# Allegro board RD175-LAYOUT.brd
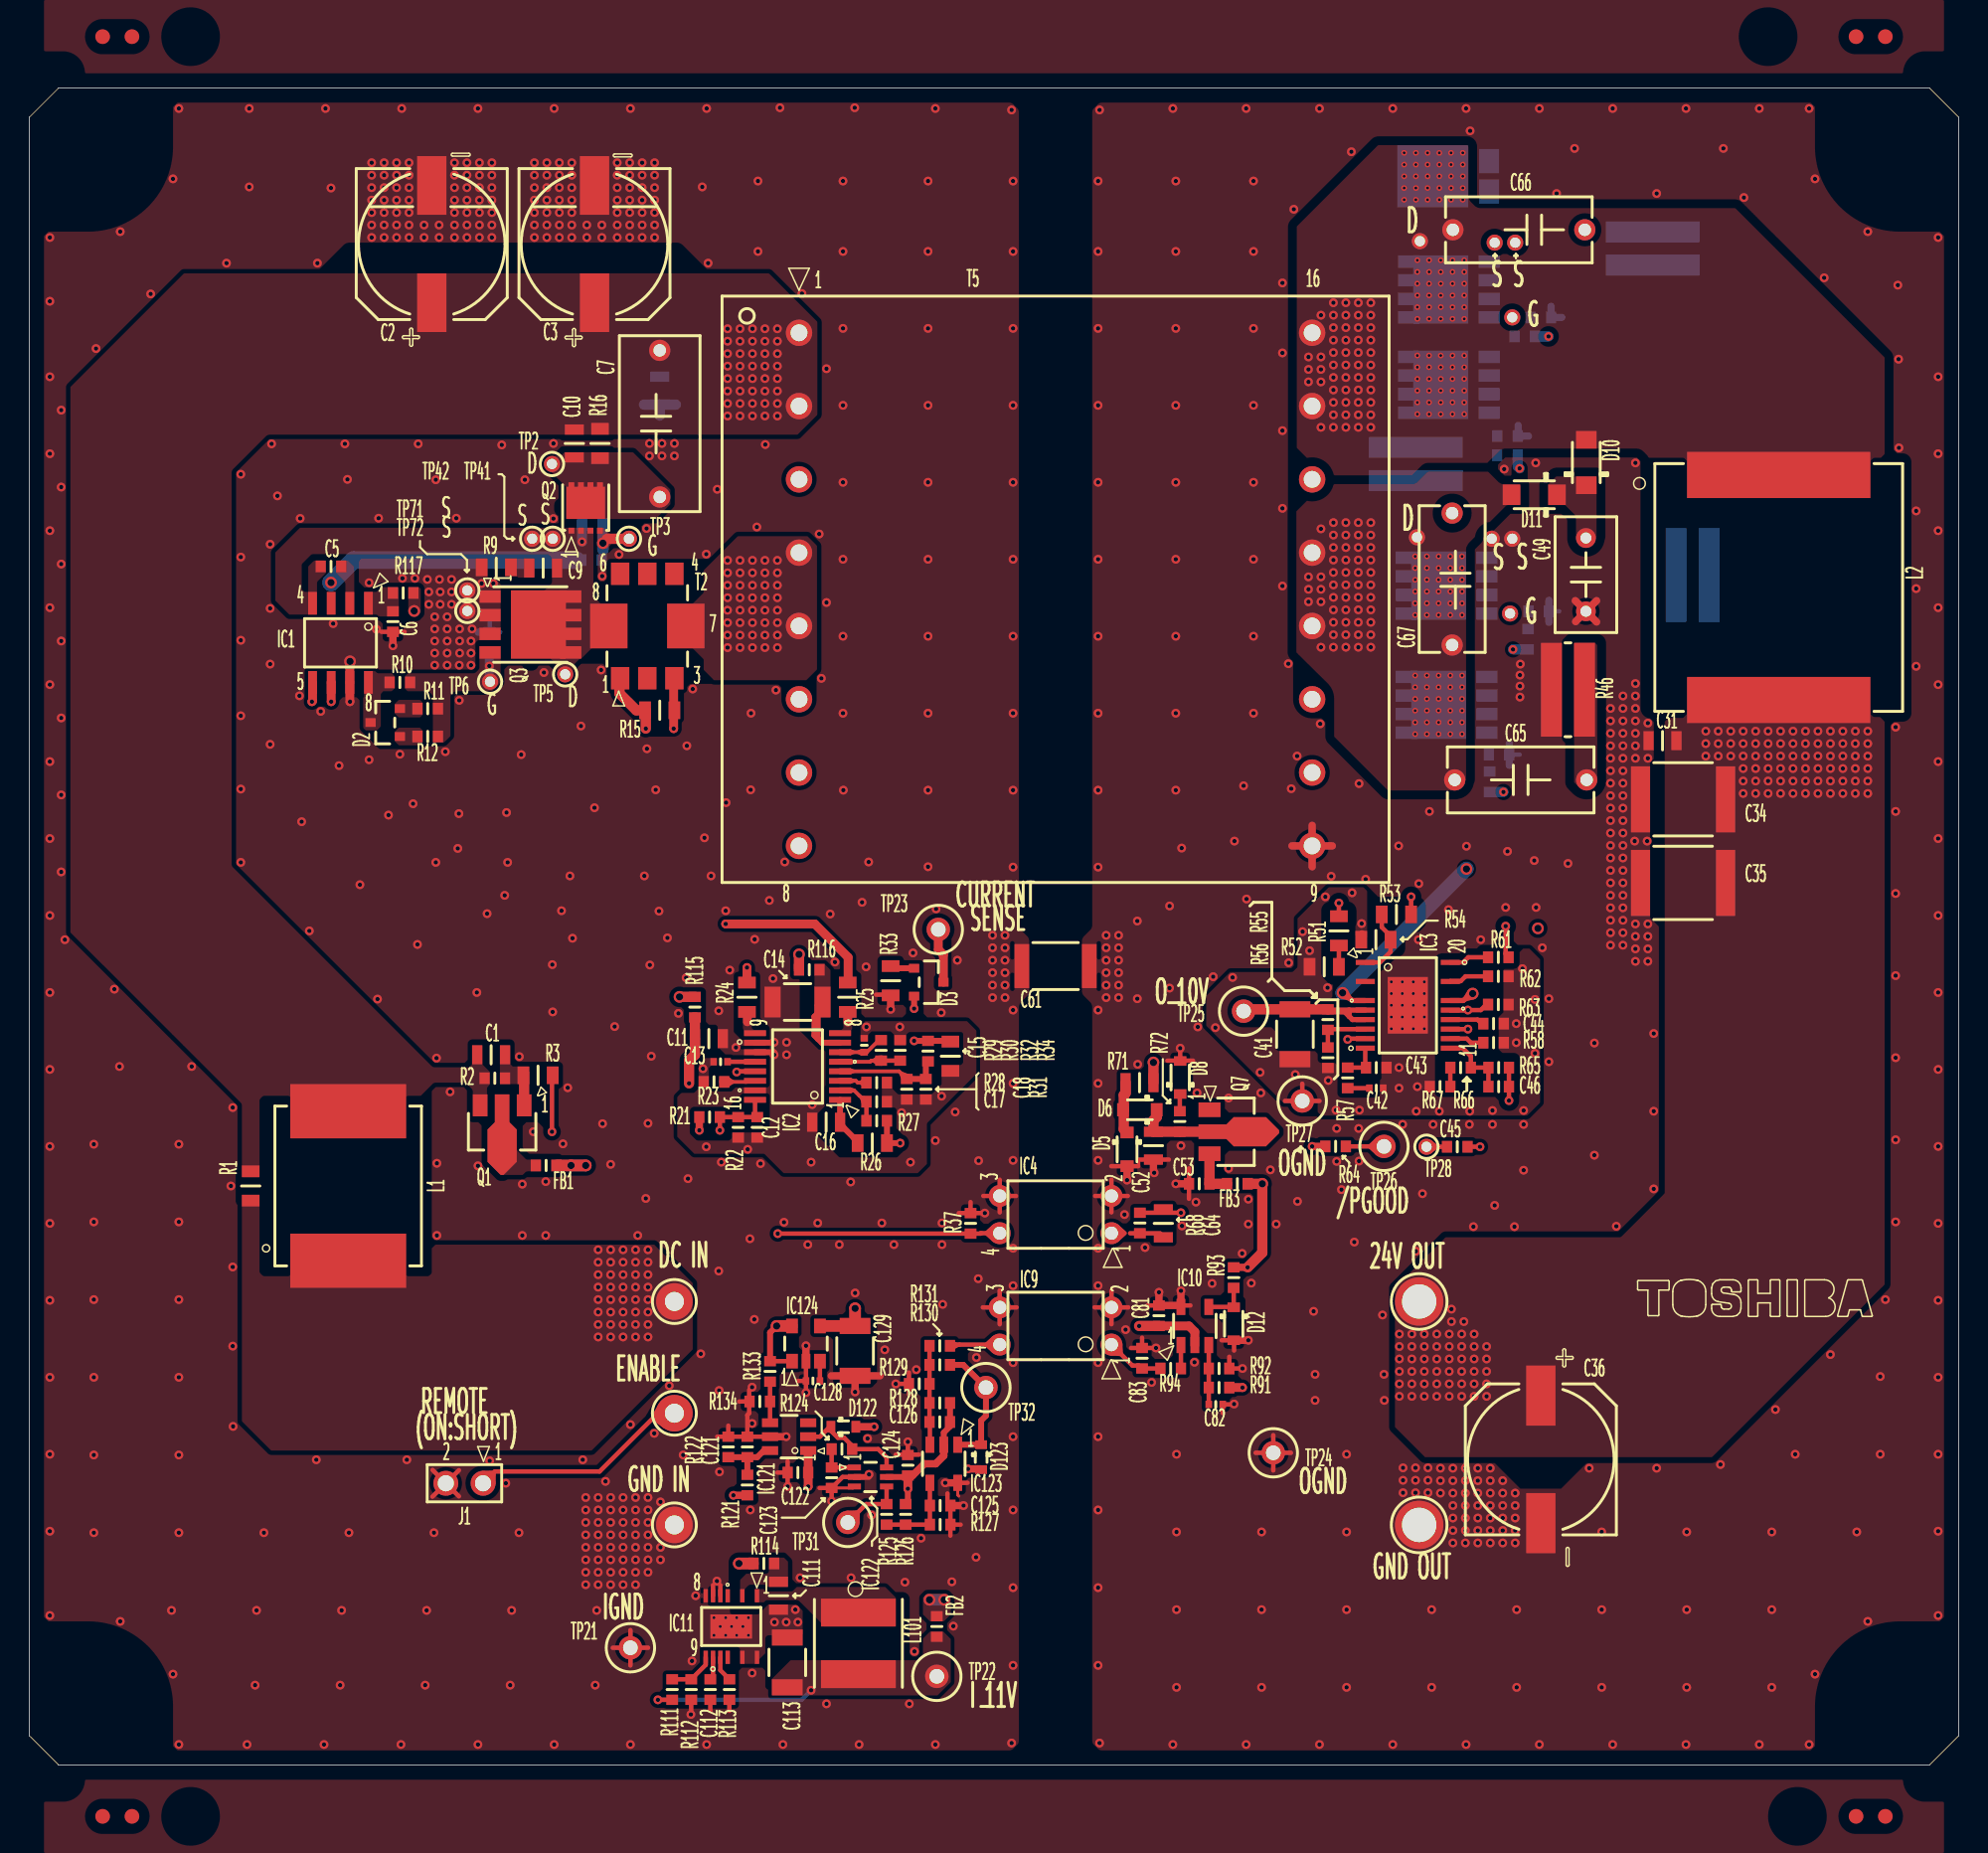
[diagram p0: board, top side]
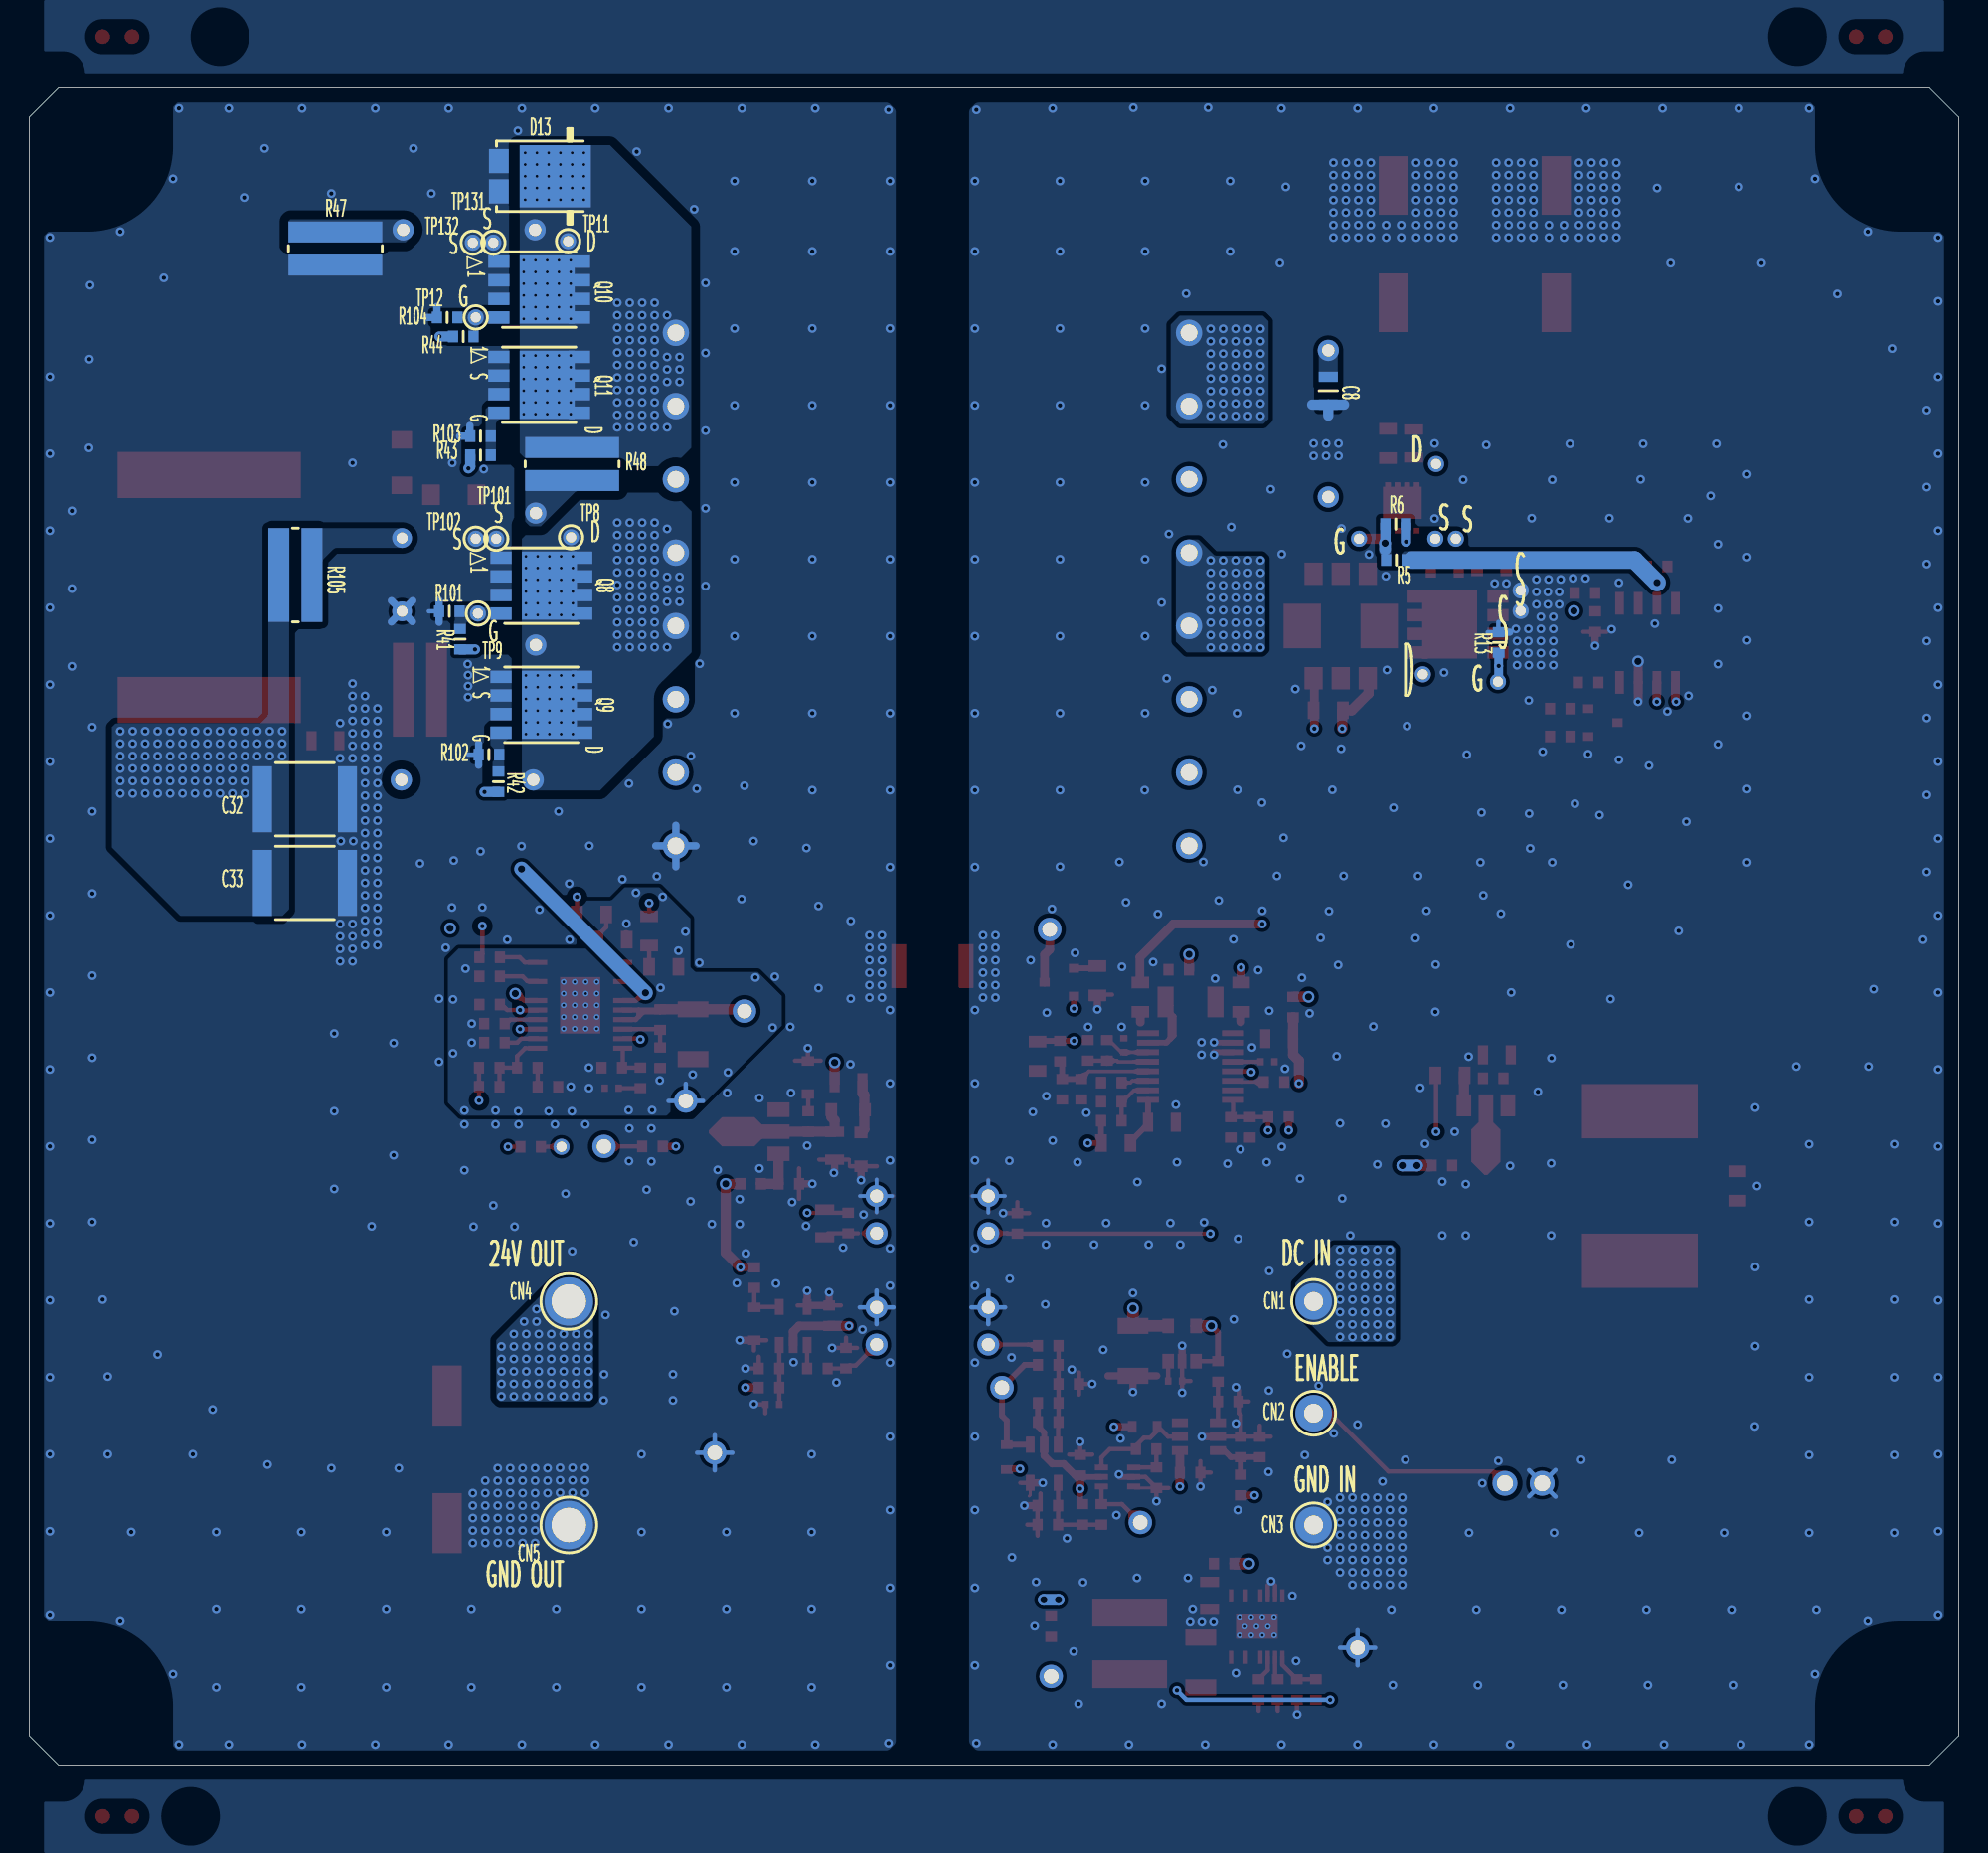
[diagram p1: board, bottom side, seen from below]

Outline 131.6 x 114.4 mm; copper layers: TOP, CONDUCTIVE2, CONDUCTIVE3, BOTTOM. Coordinates in mm from the lower left corner of the outline.
Outline path: 0,112.4 2,114.4 129.6,114.4 131.6,112.4 131.6,2 129.6,0 2,0 0,2 0,112.4

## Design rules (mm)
constraint set DEFAULT: 

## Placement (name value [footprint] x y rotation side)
C1  -  [CHIP2012_GS_1]  31.5 48.45 0 top
C2  -  [AC_S_10X12_7L_NC_2]  27.45 103.75 0 top
C3  -  [AC_S_10X12_7L_NC_2]  38.55 103.75 0 top
C5  -  [CHIP1608_GS_1]  20.57 81.76 180 top
C6  -  [CHIP1608_GS_1]  24.8 78 90 top
C7  -  [C_I_ECQE2224_F_PN]  43 91.5 270 top
C8  -  [CHIP2012_GS_1]  43 93.75 270 bottom
C9  -  [CHIP2012_GS_1]  35.05 81.65 180 top
C10  -  [CHIP2012_GS_1]  37.17 90.15 270 top
C11  -  [CHIP2012_GS_1]  46.35 49.55 0 top
C12  -  [CHIP1608_GS_1]  49.65 43.5 90 top
C13  -  [CHIP1005_GS_2]  47.15 47.98 0 top
C14  -  [CHIP3225_GS]  52.4 52.05 0 top
C15  -  [CHIP1005_GS_2]  56.95 49.1 270 top
C16  -  [CHIP2012_GS_1]  54.35 43.85 180 top
C17  -  [CHIP1608_GS_1]  57.8 45.25 180 top
C18  -  [CHIP1608_GS_1]  59.85 46.1 270 top
C31  -  [CHIP2012_GS_1]  111.4 69.88 180 top
C32  -  [CHIP5750_TD]  112.8 65.88 180 bottom
C33  -  [CHIP5750_TD]  112.8 60.17 180 bottom
C34  -  [CHIP5750_TD]  112.8 65.88 180 top
C35  -  [CHIP5750_TD]  112.8 60.17 180 top
C36  -  [AC_S_10X12_5L_PN]  103.1 20.85 180 top
C41  -  [CHIP3225_GS]  86.33 49.85 90 top
C42  -  [CHIP1005_GS_2]  91.88 46.17 0 top
C43  -  [CHIP1608_GS_1]  91.88 47.58 0 top
C44  -  [CHIP1608_GS_1]  99.88 50.58 0 top
C45  -  [CHIP1608_GS_1]  97.4 42.17 180 top
C46  -  [CHIP1608_GS_1]  100.22 46.27 180 top
C49  -  [C_I_ECQE2103_B_PN]  106.17 81.2 90 top
C52  -  [CHIP2012_GS_1]  76.67 42.25 270 top
C53  -  [CHIP1608_GS_1]  79.8 39.65 180 top
C61  -  [CHIP4632_AV]  70 54.5 0 top
C64  -  [CHIP2012_GS_1]  77.35 36.95 270 top
C65  -  [C_I_ECQE6222_F_PN]  101.72 67.2 180 top
C66  -  [C_I_ECQE6222_F_PN]  101.6 104.72 180 top
C67  -  [C_I_ECQE6222_F_PN]  97.05 80.9 270 top
C81  -  [CHIP1608_GS_1]  77.05 30.65 270 top
C82  -  [CHIP1005_GS_2]  80.92 24.6 0 top
C83  -  [CHIP1608_GS_1]  75.9 27.75 270 top
C111  -  [CHIP2012_GS_1]  51.1 11.55 270 top
C112  -  [CHIP1608_GS_1]  46.45 5.15 90 top
C113  -  [CHIP3225_GS]  51.7 7 90 top
C121  -  [CHIP1608_GS_1]  48.98 21.7 270 top
C122  -  [CHIP1608_GS_1]  52.42 19.95 180 top
C123  -  [CHIP1608_GS_1]  54.73 19.6 90 top
C124  -  [CHIP1608_GS_1]  59.92 20.45 90 top
C125  -  [CHIP1608_GS_1]  62.12 17.7 180 top
C126  -  [CHIP1608_GS_1]  62.1 23.4 0 top
C128  -  [CHIP1005_GS_2]  53.45 26.2 0 top
C129  -  [CHIP3225_GS]  56.33 28.25 90 top
CN1  -  [TP_I_6834_0_00__00_0_1]  44 31.62 90 bottom
CN2  -  [TP_I_6834_0_00__00_0_1]  44 24 270 bottom
CN3  -  [TP_I_6834_0_00__00_0_1]  44 16.38 270 bottom
CN4  -  [TP_I_8237_0_05__00_0_1]  94.8 31.62 180 bottom
CN5  -  [TP_I_8237_0_05__00_0_1]  94.8 16.38 180 bottom
D2  -  [DI_S_SOT23_3_0_95_TS]  24.27 71.11 90 top
D3  -  [DI_S_SOT23_3_0_95_TS]  61.35 53.4 270 top
D5  -  [DI_S_SOD323_2_TS_A]  74.88 42 270 top
D6  -  [DI_S_SOD323_2_TS_A]  75.75 44.7 180 top
D8  -  [ZD_S_SOD323_2_OS_A]  78.5 46.9 90 top
D10  -  [DI_S_SOD123W_TW]  106.2 88.85 90 top
D11  -  [DI_S_SOD123W_TW]  102.65 86.65 180 top
D12  -  [ZD_S_SOD323_2_OS_A]  82.15 30.1 270 top
D13  -  [DI_S_FSV10150V_OS]  96.78 108.38 0 bottom
D122  -  [DI_S_SOD523_2_RM]  55.52 23.07 180 top
D123  -  [DI_S_SOD523_2_RM]  64.92 21 90 top
FB1  -  [CHIP1608_GS_1]  35.25 40.9 0 top
FB2  -  [CHIP1608_GS_1]  61.9 9.45 270 top
FB3  -  [CHIP1608_GS_1]  82.4 39.65 180 top
IC1  -  [IC_S_SOP_8_1_27_TI]  21.23 76.55 180 top
IC2  -  [IC_S_SOP_16_0_65_GS__1]  52.4 47.65 90 top
IC3  -  [IC_S_SOP_16_20_E_0_6_1]  94.03 51.83 270 top
IC4  -  [PH_I_TLP785_TS_1]  70 37.55 90 top
IC9  -  [PH_I_TLP785_TS_1]  70 29.95 90 top
IC10  -  [IC_S_SOT23_5_0_95_TI]  79.5 29.95 0 top
IC11  -  [IC_S_SOP_16_0_5_LT_1]  47.88 9.45 180 top
IC121  -  [IC_S_SOT23_6_0_95_TI_1]  51.83 22.4 90 top
IC122  -  [IC_S_SC70_6_0_65_TI]  57.38 19.65 270 top
IC123  -  [IC_S_SOT23_5_0_95_TI]  62.38 20.55 180 top
IC124  -  [IC_S_SOP_5_0_95_TS]  52.98 28.75 0 top
J1  -  [HP_I_FFC_2AMEP1_HN]  29.68 19.22 180 top
L1  -  [L_S_ETQP5M__YLC_PN]  21.75 39.5 270 top
L2  -  [L_S_SRP1770TA_BO]  119.33 80.33 270 top
L101  -  [L_S_VLS6045EX_TD]  56.55 8.3 270 top
NOREF  -  []  109.7 30.65 0 top
NOREF#2  -  [unnamed#2]  5 117.9 0 top
NOREF#3  -  []  -5 -30 0 top
NOREF#4  -  [unnamed#2]  126.6 -3.5 180 top
NOREF#5  -  []  120.6 -3.5 0 top
NOREF#6  -  []  118.6 117.9 0 top
NOREF#7  -  []  127.6 4 0 top
NOREF#8  -  []  11 -3.5 0 top
NOREF#9  -  []  127.6 110.4 0 top
NOREF#10  -  []  4 110.4 0 top
NOREF#11  -  []  4 4 0 top
NOREF#12  -  [unnamed#2]  126.6 117.9 180 top
NOREF#13  -  []  2.35 -35.4 0 top
NOREF#14  -  [unnamed#2]  5 -3.5 0 top
NOREF#15  -  []  11 117.9 0 top
Q1  -  [TR_S_SC62_3_1_5_TS]  32.25 43.2 180 top
Q2  -  [TR_S_SON_ADVANCE_TS__1]  37.95 85.78 0 top
Q3  -  [TR_S_SOP_ADVANCE_TS__1]  34.17 77.8 270 top
Q7  -  [TR_S_SC62_3_1_5_TS]  82.3 43.2 270 top
Q8  -  [TR_S_SOP_ADVANCE_TS__1]  96.67 80.45 270 bottom
Q9  -  [TR_S_SOP_ADVANCE_TS__1]  96.67 72.33 270 bottom
Q10  -  [TR_S_SOP_ADVANCE_TS__1]  96.83 100.65 270 bottom
Q11  -  [TR_S_SOP_ADVANCE_TS__1]  96.83 94.15 270 bottom
R1  -  [CHIP2012_GS_2]  15.1 39.5 270 top
R2  -  [CHIP1608_GS_1]  31.75 46.85 0 top
R3  -  [CHIP2012_GS_2]  34.7 47.05 180 top
R5  -  [CHIP1608_GS_1]  38.35 82.2 0 bottom
R6  -  [CHIP1608_GS_1]  38.4 84.65 180 bottom
R9  -  [CHIP2012_GS_2]  31.85 81.7 180 top
R10  -  [CHIP1608_GS_1]  25.27 73.85 180 top
R11  -  [CHIP1608_GS_1]  27.18 72.06 0 top
R12  -  [CHIP1608_GS_1]  27.18 70.16 0 top
R13  -  [CHIP1608_GS_1]  31.38 76.58 90 bottom
R15  -  [CHIP2012_GS_2]  43 71.95 0 top
R16  -  [CHIP2012_GS_2]  38.92 90.15 270 top
R21  -  [CHIP1608_GS_1]  46.4 44.2 0 top
R22  -  [CHIP1608_GS_1]  48.35 43.5 270 top
R23  -  [CHIP1608_GS_1]  46.7 46.6 0 top
R24  -  [CHIP2012_GS_2]  48.95 52.38 270 top
R25  -  [CHIP2012_GS_2]  55.83 52.38 270 top
R26  -  [CHIP2012_GS_2]  57.5 42.42 180 top
R27  -  [CHIP1608_GS_1]  57.8 43.95 180 top
R28  -  [CHIP1608_GS_1]  57.8 46.55 180 top
R29  -  [CHIP1608_GS_1]  58.1 48.75 90 top
R30  -  [CHIP1608_GS_1]  59.4 48.75 270 top
R31  -  [CHIP1608_GS_1]  61.15 46.1 90 top
R32  -  [CHIP1608_GS_1]  61.3 48.7 270 top
R33  -  [CHIP2012_GS_2]  58.75 53.5 90 top
R34  -  [CHIP2012_GS_2]  62.83 48.35 270 top
R37  -  [CHIP1608_GS_1]  64.2 36.95 90 top
R41  -  [CHIP1608_GS_1]  102.22 76.8 270 bottom
R42  -  [CHIP1608_GS_1]  99.6 67.08 270 bottom
R43  -  [CHIP1608_GS_1]  100.83 89.35 0 bottom
R44  -  [CHIP1608_GS_1]  102 97.45 0 bottom
R46  -  [R_S_LTR100_RM]  104.95 73.35 180 top
R47  -  [R_S_LTR100_RM]  110.72 103.45 270 bottom
R48  -  [R_S_LTR100_RM]  94.58 88.75 270 bottom
R51  -  [CHIP2012_GS_2]  89.33 56.9 90 top
R52  -  [CHIP2012_GS_2]  88.33 54.45 0 top
R53  -  [CHIP2012_GS_2]  93.25 58.02 0 top
R54  -  [CHIP2012_GS_2]  91.85 56.3 0 top
R55  -  [CHIP1608_GS_1]  88.58 50.85 90 top
R56  -  [CHIP1608_GS_1]  88.58 48.25 90 top
R57  -  [CHIP1608_GS_1]  89.92 46.88 90 top
R58  -  [CHIP1608_GS_1]  99.88 49.27 180 top
R61  -  [CHIP1608_GS_1]  100.2 55.1 0 top
R62  -  [CHIP1608_GS_1]  100.2 53.8 0 top
R63  -  [CHIP1608_GS_1]  100.2 51.88 180 top
R64  -  [CHIP1608_GS_1]  89.1 42.2 180 top
R65  -  [CHIP1608_GS_1]  100.22 47.58 0 top
R66  -  [CHIP1608_GS_1]  97.62 47.58 0 top
R67  -  [CHIP1608_GS_1]  96.22 46.27 0 top
R68  -  [CHIP1608_GS_1]  75.75 36.98 270 top
R71  -  [CHIP2012_GS_1]  75.72 46.55 180 top
R72  -  [CHIP1608_GS_1]  78.47 43.9 270 top
R91  -  [CHIP1608_GS_1]  81.15 25.75 180 top
R92  -  [CHIP1608_GS_1]  81.15 27.05 180 top
R93  -  [CHIP1608_GS_1]  82.15 33.25 90 top
R94  -  [CHIP1608_GS_1]  77.85 27.05 0 top
R101  -  [CHIP1608_GS_1]  102.95 78.7 180 bottom
R102  -  [CHIP1608_GS_1]  100.25 68.92 180 bottom
R103  -  [CHIP1608_GS_1]  100.83 90.65 180 bottom
R104  -  [CHIP1608_GS_1]  103.1 98.75 180 bottom
R105  -  [R_S_LTR100_RM]  113.45 81.17 180 bottom
R111  -  [CHIP1608_GS_1]  43.85 5.15 270 top
R112  -  [CHIP1608_GS_1]  45.15 5.15 270 top
R113  -  [CHIP1608_GS_1]  47.75 5.15 270 top
R114  -  [CHIP1608_GS_1]  50.1 13.75 180 top
R115  -  [CHIP1608_GS_1]  45.4 51.7 90 top
R116  -  [CHIP1608_GS_1]  53.2 54.25 180 top
R117  -  [CHIP1608_GS_1]  25.5 79.95 0 top
R121  -  [CHIP1608_GS_1]  48.98 19.1 90 top
R122  -  [CHIP1608_GS_1]  47.67 21.7 90 top
R124  -  [CHIP1608_GS_1]  55.42 21.55 0 top
R125  -  [CHIP1608_GS_1]  58.48 17.1 90 top
R126  -  [CHIP1608_GS_1]  59.77 17.1 90 top
R127  -  [CHIP1608_GS_1]  62.12 16.4 180 top
R128  -  [CHIP1608_GS_1]  62.1 24.7 0 top
R129  -  [CHIP1608_GS_1]  60.7 26 0 top
R130  -  [CHIP1608_GS_1]  62.1 27.3 180 top
R131  -  [CHIP1608_GS_1]  62.1 28.6 180 top
R133  -  [CHIP1608_GS_1]  50.52 26.85 270 top
R134  -  [CHIP1608_GS_1]  49.83 24.8 180 top
T2  -  [T_S_53__C_MU]  42.15 77.7 0 top
T5  -  [T_I_BEER35_1116CPHFR_1]  70 80.2 0 top
TP2  -  [TP_I_TH0_7_LC1_1_RC1_1]  35.65 88.75 0 top
TP3  -  [TP_I_TH0_7_LC1_1_RC1_1]  40.9 83.65 0 top
TP5  -  [TP_I_TH0_7_LC1_1_RC1_1]  36.55 74.4 0 top
TP6  -  [TP_I_TH0_7_LC1_1_RC1_1]  31.43 73.9 0 top
TP8  -  [TP_I_TH0_7_LC1_1_RC1_1]  94.65 83.75 90 bottom
TP9  -  [TP_I_TH0_7_LC1_1_RC1_1]  101 78.55 270 bottom
TP11  -  [TP_I_TH0_7_LC1_1_RC1_1]  94.85 103.95 180 bottom
TP12  -  [TP_I_TH0_7_LC1_1_RC1_1]  101.15 98.75 180 bottom
TP21  -  [TP_I_LC_22_GS]  41 8 0 top
TP22  -  [TP_I_LC_22_GS]  61.9 6.05 0 top
TP23  -  [TP_I_LC_22_GS]  62 57 0 top
TP24  -  [TP_I_LC_22_GS]  84.85 21.3 0 top
TP25  -  [TP_I_LC_22_GS]  82.83 51.42 0 top
TP26  -  [TP_I_LC_22_GS]  92.4 42.2 0 top
TP27  -  [TP_I_LC_22_GS]  86.83 45.3 0 top
TP28  -  [TP_I_TH0_7_LC1_1_RC1_1]  95.3 42.17 0 top
TP31  -  [TP_I_LC_22_GS]  55.83 16.55 0 top
TP32  -  [TP_I_LC_22_GS]  65.25 25.75 0 top
TP41  -  [TP_I_TH0_7_LC1_1_RC1_1]  35.7 83.65 0 top
TP42  -  [TP_I_TH0_7_LC1_1_RC1_1]  34.3 83.65 0 top
TP71  -  [TP_I_TH0_7_LC1_1_RC1_1]  29.88 80.12 0 top
TP72  -  [TP_I_TH0_7_LC1_1_RC1_1]  29.88 78.72 0 top
TP101  -  [TP_I_TH0_7_LC1_1_RC1_1]  99.75 83.65 180 bottom
TP102  -  [TP_I_TH0_7_LC1_1_RC1_1]  101.15 83.65 180 bottom
TP131  -  [TP_I_TH0_7_LC1_1_RC1_1]  99.95 103.85 180 bottom
TP132  -  [TP_I_TH0_7_LC1_1_RC1_1]  101.35 103.85 180 bottom

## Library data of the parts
C1 C8-C11 C16 C31 C52 C64 C111 R71 = Chip2012_GS_1
C2 C3 = PCV2A180MCL1_NC
C5 C6 C12 C17 C18 C43-C46 C53 C81 C83 C112 C121-C126 FB1-FB3 R2 R5 R6 R10-R13 R21-R23 R27-R32 R37 R41-R44 R55-R58 R61-R68 R72 R91-R94 R101-R104 R111-R117 R121 R122 R124-R131 R133 R134 = Chip1608_GS_1
C7 = ECQE2224*F_PN
C13 C15 C42 C82 C128 = Chip1005_GS_2
C14 C41 C113 C129 = Chip3225_GS
C32-C35 = Chip5750_TD: alternate symbols: (C34_Chip5750_TD)
C36 = EEHZS1V331P_PN
C49 = ECQE2103*B_PN
C61 = Chip4632_AV
C65-C67 = ECQE6222*F_PN
CN1-CN3 = 6834-0-00-**-00-00-03-0_ML
CN4 CN5 = 8237-0-05-**-00-00-03-0_ML
D2 D3 = TBAT54S_TS
D5 D6 = BAS316_TS_A
D8 D12 = MM3Z***ST1G_OS_A
D10 D11 = SS220LW_TW
D13 = FSV10150V_OS: alternate symbols: (T:DI_S_FSV10150V_OS;B:DI_S_FSV10150V_OS,D13_DI_S_FSV10150V_O_1)
D122 D123 = RB520SM-30_RM
IC1 = UCC272**AD_TI
IC2 = LM5025CMTC_GS
IC3 = LT8311*FE_GS
IC4 IC9 = TLP785_TS_1
IC10 IC123 = TLV7211AIDBVR_TI
IC11 = LTC3630AIM_LT_1
IC121 = TPS3779*DBV_TI_1
IC122 = SN74LVC1G97DCK_TI
IC124 = TAR5S**_TS
J1 = FFC-2AMEP1_HN
L1 = ETQP5M***YLC_PN: alternate symbols: (L1_L_S_ETQP5M__YLC_P_1)
L2 = SRP1770TA_BO
L101 = VLS6045EX_TD
Q1 = 2SA1201_TS
Q2 = TPN5900CNH_TS
Q3 = TPH3300CNH_TS_A
Q7 = 2SC5810_TS
Q8-Q11 = TPH9R00CQH_TS_A
R1 R3 R9 R15 R16 R24-R26 R33 R34 R51-R54 = Chip2012_GS_2
R46-R48 R105 = LTR100_RM: alternate symbols: (T:R_S_LTR100_RM,R46_R_S_LTR100_RM;B:R_S_LTR100_RM,R105_R_S_LTR100_RM,R47_R_S_LTR100_RM,R48_R_S_LTR100_RM)
T2 = 53***C_MU
T5 = BEER35-1116CPHFR_GS
TP2 TP3 TP5 TP6 TP8 TP9 TP11 TP12 TP28 TP41 TP42 TP71 TP72 TP101 TP102 TP131 TP132 = TP_I_TH0.7_LC1.1_RC1.2_GS
TP21-TP27 TP31 TP32 = LC-22_GS

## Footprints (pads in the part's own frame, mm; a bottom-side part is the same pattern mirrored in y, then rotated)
AC_S_10X12_5L_PN
  rect 2x4.1 smd: 1(0,-4.35) 2(0,4.35)
AC_S_10X12_7L_NC_2
  rect 2x4 smd: 1(0,-4) 2(0,4)
C_I_ECQE2103_B_PN
  round 1.35 hole 0.75: 1(-2.5,0) 2(2.5,0)
C_I_ECQE2224_F_PN
  round 1.45 hole 0.85: 1(-5,0) 2(5,0)
C_I_ECQE6222_F_PN
  round 1.45 hole 0.85: 1(-4.5,0) 2(4.5,0)
CHIP1005_GS_2
  rect 0.45x0.5 smd: 1(-0.475,0) 2(0.475,0)
CHIP1608_GS_1
  rect 0.7x0.8 smd: 1(-0.7,0) 2(0.7,0)
CHIP2012_GS_1
  rect 0.7x1.3 smd: 1(-0.95,0) 2(0.95,0)
CHIP2012_GS_2
  rect 0.8x1.2 smd: 1(-1,0) 2(1,0)
CHIP3225_GS
  rect 1.1x2.1 smd: 1(-1.7,0) 2(1.7,0)
CHIP4632_AV
  rect 1x3 smd: 1(-2.3,0) 2(2.3,0)
CHIP5750_TD
  rect 1.3x4.5 smd: 1(-2.9,0) 2(2.9,0)
DI_S_FSV10150V_OS
  rect 1.35x1.65 smd: 1(2.8,1.035) 2(2.8,-1.035)
  custom 1.062x1.062 smd: 3(-1.05,0)
DI_S_SOD123W_TW
  rect 1.2x1.4 smd: 1(1.55,0) 2(-1.55,0)
DI_S_SOD323_2_TS_A
  rect 0.8x0.9 smd: 1(1.15,0) 2(-1.15,0)
DI_S_SOD523_2_RM
  rect 0.6x0.8 smd: 1(-0.85,0) 2(0.85,0)
DI_S_SOT23_3_0_95_TS
  rect 0.6x0.7 smd: 1(-0.95,-1) 2(0.95,-1) 3(0,1)
HP_I_FFC_2AMEP1_HN
  round 1.7 hole 1.1: 1(-1.27,0) 2(1.27,0)
IC_S_SC70_6_0_65_TI
  rect 0.4x0.9 smd: 1(-0.65,-1.1) 2(0,-1.1) 3(0.65,-1.1) 4(0.65,1.1) 5(0,1.1) 6(-0.65,1.1)
IC_S_SOP_5_0_95_TS
  rect 0.8x1 smd: 1(-0.95,-1.2) 3(0.95,-1.2) 4(0.95,1.2) 5(-0.95,1.2)
  rect 0.6x1 smd: 2(0,-1.2)
IC_S_SOP_8_1_27_TI
  rect 0.6x1.55 smd: 1(-1.905,-2.7) 2(-0.635,-2.7) 3(0.635,-2.7) 4(1.905,-2.7) 5(1.905,2.7) 6(0.635,2.7) 7(-0.635,2.7) 8(-1.905,2.7)
IC_S_SOP_16_0_5_LT_1
  rect 0.3x0.9 smd: 1(-1.76,-2.1) 3(-0.76,-2.1) 5(0.239,-2.1) 6(0.74,-2.1) 7(1.24,-2.1) 8(1.74,-2.1) 9(1.74,2.1) 10(1.24,2.1) 11(0.74,2.1) 12(0.239,2.1) 14(-0.76,2.1) 16(-1.76,2.1)
  custom 0.413x0.413 smd: EP(0,0)
IC_S_SOP_16_0_65_GS__1
  rect 0.4x1.5 smd: 1(-2.275,-2.9) 2(-1.625,-2.9) 3(-0.975,-2.9) 4(-0.325,-2.9) 5(0.325,-2.9) 6(0.975,-2.9) 7(1.625,-2.9) 8(2.275,-2.9) 9(2.275,2.9) 10(1.625,2.9) 11(0.975,2.9) 12(0.325,2.9) 13(-0.325,2.9) 14(-0.975,2.9) 15(-1.625,2.9) 16(-2.275,2.9)
IC_S_SOP_16_20_E_0_6_1
  rect 0.35x1.3 smd: 1(-2.925,-2.9) 3(-1.625,-2.9) 5(-0.325,-2.9) 6(0.325,-2.9) 7(0.975,-2.9) 8(1.625,-2.9) 9(2.275,-2.9) 10(2.925,-2.9) 11(2.925,2.9) 12(2.275,2.9) 13(1.625,2.9) 14(0.975,2.9) 15(0.325,2.9) 16(-0.325,2.9) 18(-1.625,2.9) 20(-2.925,2.9)
  custom 0.685x0.685 smd: E(0,0)
IC_S_SOT23_5_0_95_TI
  rect 0.6x1.1 smd: 1(-0.95,-1.3) 2(0,-1.3) 3(0.95,-1.3) 4(0.95,1.3) 5(-0.95,1.3)
IC_S_SOT23_6_0_95_TI_1
  rect 0.6x1.1 smd: 1(-0.95,-1.3) 2(0,-1.3) 3(0.95,-1.3) 4(0.95,1.3) 5(0,1.3) 6(-0.95,1.3)
L_S_ETQP5M__YLC_PN
  custom 0.925x0.925 smd: 1(5.1,0) 2(-5.1,0)
L_S_SRP1770TA_BO
  custom 0.787x0.787 smd: 1(-7.675,0) 2(7.675,0)
L_S_VLS6045EX_TD
  rect 1.9x5.1 smd: 1(-2.1,0) 2(2.1,0)
PH_I_TLP785_TS_1
  round 1.5 hole 0.9: 1(-1.27,-3.81) 2(1.27,-3.81) 3(1.27,3.81) 4(-1.27,3.81)
R_S_LTR100_RM
  custom 0.357x0.357 smd: 1(-1.13,0) 2(1.13,0)
T_I_BEER35_1116CPHFR_1
  round 1.8 hole 1.15: 1(-17.5,17.5) 2(-17.5,12.5) 3(-17.5,7.5) 4(-17.5,2.5) 5(-17.5,-2.5) 6(-17.5,-7.5) 7(-17.5,-12.5) 8(-17.5,-17.5) 9(17.5,-17.5) 10(17.5,-12.5) 11(17.5,-7.5) 12(17.5,-2.5) 13(17.5,2.5) 14(17.5,7.5) 15(17.5,12.5) 16(17.5,17.5)
T_S_53__C_MU
  custom 0.312x0.312 smd: 1(-1.85,-3.562) 2(0,-3.562) 3(1.85,-3.562) 4(1.85,3.562) 5(0,3.562) 6(-1.85,3.562)
  custom 0.637x0.637 smd: 7(2.625,0) 8(-2.625,0)
TP_I_6834_0_00__00_0_1
  round 2.5 hole 1.3: 1(0,0)
TP_I_8237_0_05__00_0_1
  round 3.3 hole 2.34: 1(0,0)
TP_I_LC_22_GS
  round 1.6 hole 1: 1(0,0)
TP_I_TH0_7_LC1_1_RC1_1
  round 1.1 hole 0.7: 1(0,0)
TR_S_SC62_3_1_5_TS
  rect 1x1.5 smd: 1(-1.5,-1.8) 3(1.5,-1.8)
  custom 0.5x0.5 smd: 2(0,0.2)
TR_S_SON_ADVANCE_TS__1
  rect 0.4x0.4 smd: (-0.975,1.525) (-0.975,-1.575) (-0.325,1.525) (0.325,1.525) (0.325,-1.575) (0.975,1.525) G(0.975,-1.575) S(-0.325,-1.575)
  custom 0.55x0.55 smd: D(0,0.325)
TR_S_SOP_ADVANCE_TS__1
  rect 0.85x1.45 smd: (-1.905,2.75) (-1.905,-2.75) (-0.635,2.75) (0.635,2.75) (0.635,-2.75) (1.905,2.75) G(1.905,-2.75) S(-0.635,-2.75)
  custom 0.938x0.938 smd: D(0,0.55)
unnamed#2
  round 1 smd: (0,0) (2,0)
ZD_S_SOD323_2_OS_A
  rect 0.65x0.85 smd: 1(1.125,0) 2(-1.125,0)

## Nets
VIN: FB1.2 R114.2 R115.2 R121.1
I_11V: FB2.1 IC124.1 IC124.5 R116.2 R117.2 R133.1
IGND: C2.2 C3.2 C6.1 C8.2 C11.2 C12.1 C13.1 C14.1 C15.1 C16.2 C17.1 C18.2 C61.1 C111.2 C112.1 C113.2 C121.1 C122.2 C123.1 C124.2 C125.1 C128.1 C129.1 CN3.1 IC1.7 IC2.10 IC2.11 IC2.15 IC4.3 IC9.3 IC11.6 IC11.7 IC11.8 IC11.14 IC11.16 IC11.EP IC121.5 IC122.2 IC122.3 IC123.5 IC124.2 J1.2 Q3.S R9.2 R13.2 R15.1 R22.2 R23.1 R28.1 R30.1 R31.1 R33.1 R34.2 R37.2 R112.2 R113.2 R122.2 R127.1 R129.1 R134.2 T2.1 TP21.1 TP71.1 TP72.1
O_10V: C41.2 C81.2 FB3.1 IC3.6 IC3.7 IC10.2 R55.2 R64.2 R93.2 TP25.1
OGND: C31.2 C32.2 C33.2 C34.2 C35.2 C36.2 C41.1 C42.2 C43.2 C44.2 C49.1 C52.2 C53.2 C61.2 C81.1 C82.2 C83.1 CN5.1 D5.1 D8.1 D12.1 D13.1 D13.2 IC3.E IC4.2 IC9.2 IC10.5 Q8.S Q9.S Q10.S Q11.S R46.2 R47.2 R52.1 R54.1 R56.1 R58.1 R62.2 R63.1 R67.1 R92.1 R101.1 R102.1 R103.1 R104.1 T5.9 TP24.1 TP27.1 TP101.1 TP102.1 TP131.1 TP132.1
N551925: Q10.G R44.1 R104.2 TP12.1
N551939: C66.2 D10.1 D13.3 L2.1 Q10.D Q11.D R48.1 R53.2 R61.2 T5.15 T5.16 TP11.1
N551985: T2.7 T5.4 T5.5
N552199: C31.1 C32.1 C33.1 C34.1 C35.1 C36.1 C46.1 CN4.1 L2.2 R65.2 R91.1 R105.1
N552352: C1.1 C2.1 C3.1 C7.1 C8.1 C10.1 L1.2 Q1.3 R1.1 R2.1 R16.1 T5.1 T5.2
N552464: C65.2 C67.2 D11.1 Q8.D Q9.D R51.2 T5.12 T5.13 TP8.1
N552846: R71.1 T5.10
N556504: Q9.G R42.1 R102.2
N560012: Q8.G R41.1 R101.2 TP9.1
N560018: Q2.G R5.2 R6.1 TP3.1
N560020: IC1.6 R25.1
N560028: C1.2 Q1.1 R2.2 R3.2
N560032: C52.1 D6.2 Q7.2 R72.2
N560040: IC3.8 R55.1 R56.2
N560044: IC3.16 R43.2 R44.2
N560052: IC2.9 R24.2
N560054: FB1.1 Q1.2
N560056: Q3.G R10.1 R11.2 R12.2 R13.1 TP6.1
N560060: C121.2 IC121.6 R121.2 R122.1
N560066: C64.1 IC3.9 R68.1
N560076: C5.2 C9.1 IC1.4 Q2.S Q3.D R6.2 T2.8 TP5.1 TP41.1 TP42.1
N560080: IC3.5 R41.2 R42.2
N560082: IC3.18 R62.1
N560106: C53.1 FB3.2 Q7.3
N560114: C44.1 IC3.14
N560120: D3.3 R15.2 T2.3 TP23.1
N560124: C45.1 IC3.15 R63.2
N560134: C11.1 R21.1 R26.1 R27.1 R115.1
N560136: C64.2 IC4.1 R68.2
N560152: IC3.13 R64.1 TP26.1
N560170: IC3.3 R51.1 R52.2
N560174: D2.3 IC1.8 R10.2
N560178: C46.2 IC3.11 R65.1 R66.2
N560180: C122.1 C124.1 C126.2 C129.2 IC121.1 IC122.5 IC123.2 IC124.4 R126.2 R128.2
N560194: C43.1 IC3.10 R57.2
N560196: C7.2 C10.2 Q2.D R16.2 TP2.1
N560198: C13.2 IC2.12
N560204: C12.2 D122.1 D123.1 IC2.16 R21.2 R22.1
N560212: R66.1 R67.2
N560214: C113.1 FB2.2 L101.2 R111.2 TP22.1
N560216: D2.2 R11.1
N560218: D3.1 R33.2
N560224: Q11.G R43.1 R103.2
N560238: C18.1 IC2.4 R31.2 R32.2
N560240: IC3.12 R58.2
N560246: IC2.3 R28.2
N560250: D8.2 Q7.1 R72.1
N560270: C15.2 IC2.6 R29.2
N560286: C6.2 IC1.1 R117.1
N560290: C14.2 IC2.7 R116.1
N560306: IC2.13 IC4.4 R37.1
N560310: CN1.1 L1.1 R1.2
N560318: C5.1 IC1.2
N560366: IC1.3 R5.1
N560368: IC2.5 R29.1 R30.2
N560372: IC3.1 R53.1 R54.2
N560402: CN2.1 J1.1 R3.1
N560442: C17.2 IC2.2 R27.2
N560448: D5.2 D6.1 R71.2
N560522: D3.2 R32.1 R34.1
N560530: IC2.14 R23.2
N560656: D2.1 R12.1
N560660: IC2.8 R25.2
N560674: C42.1 R57.1
N560710: C16.1 IC2.1 R26.2
N560758: IC1.5 R24.1
N560892: IC3.20 R61.1
N568590: D122.2 IC121.2 IC122.6 R124.2
N568875: C123.2 IC122.1 R124.1
N570936: IC122.4 R125.2 TP31.1
N571063: C125.2 IC123.4 R125.1 R126.1 R127.2
N572220: C126.1 IC123.3 R128.1 R129.2 R130.2 R131.2
N572478: D123.2 IC123.1 R130.1 TP32.1
N585143: C82.1 IC10.3 R91.2 R92.2
N585161: D12.2 IC10.4 R93.1
N585197: C83.2 IC9.1 R94.1
N585311: IC10.1 R94.2
N641223: IC9.4 R131.1
N642654: C49.2 D10.2 D11.2 R105.2
N647990: C45.2 TP28.1
N3796628: C67.1 R48.2
N3799991: C65.1 R46.1
N3800429: C66.1 R47.1
N3802771: IC121.4 R133.2 R134.1
N3804597: IC11.1 L101.1
N3804695: C111.1 IC11.3 R114.1
N3805483: IC11.9 R111.1 R112.1
N3805587: C112.2 IC11.10
N3805628: IC11.11 R113.1
N3830864: C128.2 IC124.3
N3881286: C9.2 R9.1

Pads without a net: IC11 5 12; IC121 3; T2 2 4 5 6; T5 3 6 7 8 11 14

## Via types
v1: diameter 0.6, hole 0.3, TOP to BOTTOM, 1352 vias
v2: diameter 0.8, hole 0.5, TOP to BOTTOM, 19 vias
v3: diameter 0.4, hole 0.2, TOP to BOTTOM, 181 vias

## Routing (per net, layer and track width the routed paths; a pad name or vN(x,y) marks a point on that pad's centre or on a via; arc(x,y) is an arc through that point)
VIN: length 56.2
  TOP w0.5: R121.1 v1(48.02,18.4)
  TOP w0.7: R115.2 v2(44.35,52.4)
  TOP w0.8: v2(37.95,40.9) v2(36.95,40.9) 36.02,40.9 ; 49.35,13.75 v2(48.4,13.75)
  CONDUCTIVE2 w0.8: v2(36.95,40.9) v2(37.95,40.9)
  CONDUCTIVE3 w1: v2(37.95,40.9) 40.25,43.2 40.25,49.1 43.55,52.4 v2(44.35,52.4) ; v2(37.95,40.9) 39,39.85 42.55,39.85 48.2,34.2 48.2,18.57 v1(48.02,18.4) 48.02,14.12 v2(48.4,13.75) ; v2(37.95,40.9) v2(36.95,40.9)
  BOTTOM w0.8: v2(36.95,40.9) v2(37.95,40.9)
I_11V: length 129.4
  TOP w0.3: IC124.1 R133.1
  TOP w0.4: R133.1 50.52,29.5 v2(50.98,29.95)
  TOP w0.7: R116.2 v2(52.5,55.3)
  TOP w0.8: v2(50.98,29.95) 52,29.95
  CONDUCTIVE2 w0.8: v2(61.4,11.28) v2(62.4,11.28)
  CONDUCTIVE3 w1.2: v2(50.98,29.95) 50.45,29.43 50.45,16.7 55.88,11.28 v2(61.4,11.28) v2(62.4,11.28) 63.4,11.28 65.78,13.65 65.78,22 62.75,25.02 62.75,30.07 63.55,30.88 63.55,42.5 58.48,47.58 58.15,47.58 52.5,53.23 v2(52.5,55.3) 48.33,59.48 36.38,59.48 26.25,69.6 26.25,78.6
  BOTTOM w0.8: v2(62.4,11.28) v2(61.4,11.28)
  vias: v2(26.25,78.72)
IGND: length 176.7
  TOP w0.2: 63.4,18.35 63.33,18.43 IC123.5 ; IC122.3 56.17,18.9 C123.1
  TOP w0.3: C123.1 55.48,19.65 IC122.2 ; C123.1 v1(54.73,18) ; C123.1 53.9,18.9 ; 48.42,24.8 49.1,24.8 ; 49.1,24.8 49.1,25.57 ; 49.1,24.8 49.1,24 48.98,23.88 C121.1 ; IC4.3 66.19,39.92 ; IC4.3 66.19,37.7 ; IC4.3 65.08,38.82 ; IC4.3 67.3,38.82 ; R122.2 47.67,23.15 ; R122.2 46.92,22.4 ; R122.2 C121.1 ; TP21.1 41,9.2 ; TP21.1 39.8,8 ; TP21.1 42.2,8 ; TP21.1 41,6.8 ; C122.2 51.73,20.73 ; C122.2 v1(51.73,19) ; C122.2 51.02,19.95 ; 25.6,77.3 C6.1 24.02,77.3 ; R127.1 63.52,16.4 ; R127.1 62.83,15.65 ; R127.1 C125.1 62.62,17.9 62.62,18.52 ; 59.92,21.18 v1(59.92,22.05) ; 59.92,21.18 60.67,21.18 ; 59.92,21.18 59.1,21.18 ; C121.1 50.5,22.4 ; J1.2 27.5,20.12 ; J1.2 27.5,18.31 ; J1.2 29.3,18.33 ; J1.2 29.3,20.11 ; 45.15,4.46 45.15,3.7 ; R37.2 v1(65.17,37.65) ; R37.2 63.4,37.65 ; R37.2 64.2,38.4 ; IC9.3 67.34,31.22 ; IC9.3 66.19,32.37 ; IC9.3 66.19,30.07 ; IC9.3 65.04,31.22 ; 57.75,52.55 58.75,52.55 ; C112.1 46.45,3.7 ; R113.2 47.75,3.7 ; IC11.7 46.64,12.28 ; C128.1 IC124.2 ; C128.1 52.4,26.2 ; C128.1 v1(52.98,25.4) ; IC123.5 64,19.25 ; R129.1 60,26.77 ; R129.1 v1(59.1,26) ; R129.1 60,25.27 ; IC11.6 47.14,12.28
  TOP w0.4: IC122.2 57.25,19.65 ; IC2.10 50.8,49.27 ; IC2.11 50.8,48.62 v1(50.8,48.45)
  TOP w0.5: C129.1 54.7,26.55 ; C129.1 v1(56.33,25.45) ; C129.1 58.02,26.55 ; C6.1 v1(24.8,76.35) ; v1(63.73,17.7) C125.1 ; 50.5,22.4 v1(51.62,22.4) ; 58.75,51.65 R33.1 58.75,52.55 ; v1(52.98,28.6) IC124.2 ; v1(62.48,19.25) IC123.5
  TOP w0.6: 21.86,72.54 IC1.7 21.86,75.29
  TOP w0.7: 40.25,74.14 40.25,73.1 41.4,71.95 R15.1 42.05,71.95 v1(42.05,70.7)
  CONDUCTIVE2 w0.25: IC4.3 65.08,38.82 ; IC4.3 67.3,38.82 ; IC4.3 66.19,37.7 ; IC4.3 66.19,39.92
  CONDUCTIVE2 w0.3: J1.2 29.3,20.11 ; J1.2 27.5,18.31 ; J1.2 27.5,20.12 ; J1.2 29.3,18.33 ; TP21.1 39.8,8 ; TP21.1 41,9.2 ; TP21.1 42.2,8 ; TP21.1 41,6.8 ; IC9.3 66.19,32.37 ; IC9.3 67.34,31.22 ; IC9.3 66.19,30.07 ; IC9.3 65.04,31.22
  CONDUCTIVE3 w0.25: IC4.3 66.19,37.73 ; IC4.3 65.05,38.82 ; IC4.3 66.19,39.92 ; IC4.3 67.28,38.82
  CONDUCTIVE3 w0.3: IC9.3 65.04,31.22 ; IC9.3 66.19,30.07 ; IC9.3 67.34,31.22 ; IC9.3 66.19,32.37 ; J1.2 27.5,18.31 ; J1.2 29.3,18.33 ; J1.2 29.3,20.11 ; J1.2 27.5,20.12 ; TP21.1 42.2,8 ; TP21.1 41,9.2 ; TP21.1 41,6.8 ; TP21.1 39.8,8
  CONDUCTIVE3 w0.7: v1(42.05,70.7) 43.05,69.7 43.05,67.58 50.8,59.83 57.17,59.83 61.25,55.75 61.25,46.6 v1(62.23,45.62)
  BOTTOM w0.25: IC4.3 66.19,37.67 ; IC4.3 65.05,38.82 ; IC4.3 66.19,39.9 ; IC4.3 67.28,38.82
  BOTTOM w0.3: IC9.3 66.19,32.37 ; IC9.3 65.04,31.22 ; IC9.3 66.19,30.07 ; IC9.3 67.34,31.22 ; 31.4,77.97 31.4,77.28 32.12,77.28 ; TP21.1 41,9.2 ; TP21.1 41,6.8 ; TP21.1 39.8,8 ; TP21.1 42.2,8 ; J1.2 29.3,20.11 ; J1.2 27.5,18.31 ; J1.2 27.5,20.12 ; J1.2 29.3,18.33
  BOTTOM w0.5: 30.62,77.28 R13.2 31.4,77.28
  BOTTOM w0.7: C8.2 44.1,92.8 ; C8.2 43,92.05 ; C8.2 41.92,92.8
  vias: v1(1.4,104.2) v1(1.4,99.85) v1(1.4,94.7) v1(1.4,89.45) v1(1.4,84.2) v1(1.4,78.95) v1(1.4,73.7) v1(1.4,68.45) v1(1.4,63.2) v1(1.4,57.95) v1(1.4,52.7) v1(1.4,47.45) v1(1.4,42.2) v1(1.4,36.95) v1(1.4,31.7) v1(1.4,26.45) v1(1.4,21.2) v1(1.4,15.95) v1(1.4,10.2) v1(2.17,92.42) v1(2.17,87.17) v1(2.17,81.92) v1(2.17,76.67) v1(2.17,71.42) v1(2.17,66.17) v1(2.17,60.92) v1(2.42,56.3) v1(4.4,42.35) v1(4.4,37.05) v1(4.4,31.75) v1(4.4,26.45) v1(4.4,21.15) v1(4.4,15.85) v1(4.55,96.62) v1(5.8,52.92) v1(6.2,104.6) v1(6.15,47.65) v1(6.2,9.8) v1(8.28,100.35) v1(9.7,10.55) v1(9.8,108.2) v1(9.8,6.2) v1(10.2,113) v1(10.2,42.35) v1(10.2,37.05) v1(10.2,31.75) v1(10.2,26.45) v1(10.2,21.15) v1(10.2,15.85) v1(10.2,1.4) v1(11.07,47.65) v1(13.45,102.45) v1(13.75,39.5) v1(13.88,44.85) v1(13.88,33.98) v1(13.88,28.57) v1(13.9,23.1) v1(14.43,88.05) v1(14.43,82.4) v1(14.43,76.72) v1(14.43,71.58) v1(14.43,66.58) v1(14.43,61.58) v1(14.85,1.4) v1(15,113) v1(15,107.65) v1(15.4,5.45) v1(15.5,10.55) v1(16,15.85) v1(16.43,83.28) v1(16.43,78.9) v1(16.43,75.1) v1(16.43,69.62) v1(16.52,90.12) v1(16.93,86.58) v1(18.43,72.94) v1(18.48,85.04) v1(18.57,64.35) v1(19.1,56.9) v1(19.65,102.45) v1(19.57,20.82) v1(19.88,71.88) v1(20.1,1.4) v1(20.2,113) v1(20.57,107.58) v1(20.73,77.86) v1(21.12,68.17) v1(21.2,5.45) v1(21.3,10.55) v1(21.52,90.12) v1(21.7,87.7) v1(21.8,15.85) v1(21.88,72.54) v1(22.55,60.05) v1(23.18,80.65) v1(23.18,68.58) v1(23.35,109.3) v1(23.35,108.45) v1(23.35,107.6) v1(23.35,106.75) v1(23.35,105.9) v1(23.35,105.05) v1(23.35,104.2) v1(23.68,77.47) v1(23.82,85.05) v1(23.75,52.25) v1(24.2,109.3) v1(24.2,108.45) v1(24.2,107.6) v1(24.2,106.75) v1(24.2,105.9) v1(24.2,105.05) v1(24.2,104.2) v1(24.5,64.8) v1(25.05,109.3) v1(25.05,108.45) v1(25.05,107.6) v1(25.05,106.75) v1(25.05,105.9) v1(25.05,105.05) v1(25.05,104.2) v1(25.27,68.95) v1(25.4,113) v1(25.45,80.95) v1(25.35,1.4) v1(25.75,20.82) v1(25.9,109.3) v1(25.9,108.45) v1(25.9,107.6) v1(25.9,106.75) v1(25.9,105.9) v1(25.9,105.05) v1(25.9,104.2) v1(26.18,65.58) v1(26.3,80.95) v1(26.52,90.12) v1(26.48,55.98) v1(26.93,105.05) v1(26.93,104.2) v1(27,5.45) v1(27.15,80.88) v1(27.1,10.55) v1(27.25,80.03) v1(27.25,79.17) v1(27.65,78.33) v1(27.65,77.5) v1(27.65,76.67) v1(27.65,75.85) v1(27.65,75.03) v1(27.6,15.85) v1(27.73,87.67) v1(27.73,61.58) v1(27.77,48.23) v1(27.8,41.05) v1(27.8,36.12) v1(27.95,105.05) v1(27.95,104.2) v1(27.98,80.88) v1(28.02,80.03) v1(28.02,79.17) v1(28.38,69.12) v1(28.5,78.33) v1(28.5,77.5) v1(28.5,76.67) v1(28.5,75.85) v1(28.5,75.03) v1(28.7,45.92) v1(28.8,80.88) v1(28.8,80.03) v1(28.8,79.17) v1(29,109.3) v1(29,108.45) v1(29,107.6) v1(29,106.75) v1(29,105.9) v1(29,105.05) v1(29,104.2) v1(29.12,85.05) v1(29.23,62.52) v1(29.32,75.03) v1(29.32,72.62) v1(29.3,64.9) v1(29.35,77.5) v1(29.35,76.67) v1(29.35,75.85) v1(29.85,109.3) v1(29.85,108.45) v1(29.85,107.6) v1(29.85,106.75) v1(29.85,105.9) v1(29.85,105.05) v1(29.85,104.2) v1(30.12,76.67) v1(30.12,75.85) v1(30.12,75.03) v1(30.2,77.5) v1(30.52,52.7) v1(30.6,113) v1(30.6,40.88) v1(30.6,1.4) v1(30.7,109.3) v1(30.7,108.45) v1(30.7,107.6) v1(30.7,106.75) v1(30.7,105.9) v1(30.7,105.05) v1(30.7,104.2) v1(30.85,80.6) v1(31.23,58.08) v1(31.4,20.75) v1(31.55,109.3) v1(31.55,108.45) v1(31.55,107.6) v1(31.55,106.75) v1(31.55,105.9) v1(31.55,105.05) v1(31.55,104.2) v1(31.65,80.6) v1(32.23,90.05) v1(32.42,59.33) v1(32.55,64.97) v1(32.5,19.23) v1(32.62,61.58) v1(32.8,5.45) v1(32.9,10.55) v1(33.42,48.33) v1(33.4,15.85) v1(33.55,68.92) v1(33.62,39.62) v1(33.62,36.12) v1(33.8,87.67) v1(34.38,43.2) v1(34.45,109.3) v1(34.45,108.45) v1(34.45,107.6) v1(34.45,106.75) v1(34.45,105.9) v1(34.45,105.05) v1(34.45,104.2) v1(35.1,74.53) v1(35.23,39.8) v1(35.23,36.12) v1(35.3,109.3) v1(35.3,108.45) v1(35.3,107.6) v1(35.3,106.75) v1(35.3,105.9) v1(35.3,105.05) v1(35.3,104.2) v1(35.67,54.6) v1(35.7,51.38) v1(35.8,113) v1(35.75,90.15) v1(35.75,85.03) v1(35.8,1.4) v1(36.15,109.3) v1(36.15,108.45) v1(36.15,107.6) v1(36.15,106.75) v1(36.15,105.9) v1(36.15,105.05) v1(36.15,104.2) v1(36.3,58.27) v1(36.4,42.38) v1(36.73,46.2) v1(36.88,60.65) v1(37,109.3) v1(37,108.45) v1(37,107.6) v1(37,106.75) v1(37,105.9) v1(37,105.05) v1(37,104.2) v1(37.05,56.4) v1(37.62,70.88) v1(37.75,20.82) v1(38.02,105.05) v1(38.02,104.2) v1(37.95,18.25) v1(37.95,17.4) v1(37.95,16.55) v1(37.95,15.7) v1(37.95,14.85) v1(37.95,14) v1(37.95,13.15) v1(37.95,12.3) v1(38.55,65.3) v1(38.6,5.45) v1(38.7,10.55) v1(38.8,18.25) v1(38.8,17.4) v1(38.8,16.55) v1(38.8,15.7) v1(38.8,14.85) v1(38.8,14) v1(38.8,13.15) v1(38.8,12.3) v1(39.05,105.05) v1(39.05,104.2) v1(39,74.7) v1(39.08,81.1) v1(39.1,43.75) v1(39.3,19.35) v1(39.65,40.98) v1(39.65,18.25) v1(39.65,17.4) v1(39.65,16.55) v1(39.65,15.7) v1(39.65,14.85) v1(39.65,14) v1(39.65,13.15) v1(39.65,12.3) v1(39.92,50.38) v1(40.1,109.3) v1(40.1,108.45) v1(40.1,107.6) v1(40.1,106.75) v1(40.1,105.9) v1(40.1,105.05) v1(40.1,104.2) v1(40.23,82.58) v1(40.5,18.25) v1(40.5,17.4) v1(40.5,16.55) v1(40.5,15.7) v1(40.5,14.85) v1(40.5,14) v1(40.5,13.15) v1(40.5,12.3) v1(41,113) v1(40.95,109.3) v1(40.95,108.45) v1(40.95,107.6) v1(40.95,106.75) v1(40.95,105.9) v1(40.95,105.05) v1(40.95,104.2) v1(41,23.23) v1(41,1.4) v1(41.35,18.25) v1(41.35,17.4) v1(41.35,16.55) v1(41.35,15.7) v1(41.35,14.85) v1(41.35,14) v1(41.35,13.15) v1(41.35,12.3) v1(41.5,36.12) v1(41.8,109.3) v1(41.8,108.45) v1(41.8,107.6) v1(41.8,106.75) v1(41.8,105.9) v1(41.8,105.05) v1(41.8,104.2) v1(41.95,60.65) v1(42.05,38.65) v1(42.1,84.35) v1(42.12,69.33) v1(42.2,43.77) v1(42.2,18.25) v1(42.2,17.4) v1(42.2,16.55) v1(42.2,15.7) v1(42.2,14.85) v1(42.2,14) v1(42.2,13.15) v1(42.3,90.15) v1(42.3,89.3) v1(42.33,54.58) v1(42.42,48.35) v1(42.65,109.3) v1(42.65,108.45) v1(42.65,107.6) v1(42.65,106.75) v1(42.65,105.9) v1(42.65,105.05) v1(42.65,104.2) v1(42.62,22.62) v1(42.73,66.53) v1(42.95,58.25) v1(43.05,17.95) v1(43.05,14.85) v1(43.05,14) v1(43.15,90.15) v1(43.15,89.3) v1(43.52,56.42) v1(43.65,25.88) v1(44,90.15) v1(44,89.3) v1(44.27,51.27) v1(44.6,21.15) v1(44.8,53.7) v1(44.85,69.53) v1(44.92,40) v1(45.12,3.45) v1(45.25,73.4) v1(45.2,7.1) v1(45.45,11.55) v1(45.8,28.05) v1(45.9,107.65) v1(46.05,63.25) v1(45.95,47.5) v1(46.2,113) v1(46.17,82.6) v1(46.17,42.17) v1(46.2,1.4) v1(46.3,102.45) v1(46.5,60.65) v1(46.92,87.03) v1(46.9,12.55) v1(47.02,51.45) v1(47.02,33.7) v1(47.05,25.55) v1(47.08,20) v1(47.2,41.12) v1(47.52,65.65) v1(47.5,58.27) v1(47.77,54.23) v1(48.2,48.95) v1(49,42) v1(49.15,35.9) v1(49.23,71.75) v1(49.2,66.53) v1(49.17,17.4) v1(49.3,25.77) v1(49.3,23.3) v1(49.3,6.28) v1(49.48,56.33) v1(49.45,30.4) v1(49.62,84.45) v1(49.7,108.05) v1(49.7,103.25) v1(49.88,41.02) v1(50.2,90.08) v1(50.48,58.98) v1(50.73,53.65) v1(50.8,49.3) v1(50.83,9.75) v1(50.92,73.33) v1(51.2,113.05) v1(51.4,1.4) v1(51.52,61.6) v1(51.48,37.02) v1(51.65,49.3) v1(51.65,48.45) v1(51.62,9.75) v1(52.25,10.6) v1(52.42,9.75) v1(52.58,12.78) v1(52.7,100.38) v1(53.1,35.5) v1(53.33,41.12) v1(53.4,45.05) v1(53.77,36.98) v1(53.88,83.97) v1(54.02,74.12) v1(54.38,95.25) v1(54.38,79.3) v1(54.38,4.17) v1(54.62,58.05) v1(54.95,54.77) v1(55.25,35.5) v1(55.5,108.05) v1(55.5,103.25) v1(55.5,98) v1(55.5,92.75) v1(55.5,87.5) v1(55.5,82.25) v1(55.5,77) v1(55.5,71.75) v1(55.52,66.5) v1(56.02,39.77) v1(56.05,12.78) v1(56.3,113.05) v1(56.33,32.2) v1(56.6,1.4) v1(56.8,58.85) v1(57.08,54.45) v1(57.1,50.35) v1(57.25,61.6) v1(57.17,22.27) v1(57.27,19.82) v1(57.45,17.05) v1(58.15,36.98) v1(58.35,28.32) v1(58.75,51.55) v1(58.98,35.5) v1(59.38,50.35) v1(59.5,44.5) v1(59.73,12.47) v1(60.02,4.17) v1(60.1,41.12) v1(60.27,55.4) v1(60.38,7.75) v1(60.5,26.98) v1(60.83,15.47) v1(61.3,108.05) v1(61.3,103.25) v1(61.3,98) v1(61.3,92.75) v1(61.3,87.5) v1(61.3,82.25) v1(61.3,77) v1(61.3,71.75) v1(61.3,66.5) v1(61.3,61.27) v1(61.8,113) v1(61.8,42.6) v1(61.8,1.4) v1(61.85,58.4) v1(62.2,51.33) v1(62.25,36.98) v1(62.25,35.5) v1(62.3,31.43) v1(62.92,12.5) v1(63.02,9.47) v1(63.15,44.55) v1(63.3,54.9) v1(64.6,27.8) v1(64.58,14.18) v1(64.72,33.17) v1(64.75,41.23) v1(65.7,56.6) v1(65.7,55.75) v1(65.7,54.9) v1(65.7,54.05) v1(65.7,53.2) v1(65.7,52.35) v1(66.55,56.6) v1(66.55,55.75) v1(66.55,54.9) v1(66.55,54.05) v1(66.55,53.2) v1(66.55,52.35) v1(67,112.9) v1(67,1.5) v1(67.1,108.05) v1(67.1,103.25) v1(67.1,98) v1(67.1,92.75) v1(67.1,87.5) v1(67.1,82.25) v1(67.1,77) v1(67.1,71.75) v1(67.1,66.5) v1(67.1,61.25) v1(67.1,51.5) v1(67.1,46.5) v1(67.1,41.25) v1(67.1,35.25) v1(67.1,32.7) v1(67.1,27.45) v1(67.1,22.4) v1(67.1,17.4) v1(67.1,12.1) v1(67.1,6.8) v2(21.88,75.29) v3(46.7,10.05) v3(46.7,8.85) v3(47.12,9.45) v3(47.5,10.05) v3(47.5,8.85) v3(47.9,9.45) v3(48.25,10.05) v3(48.25,8.85) v3(48.67,9.45) v3(49.05,10.05) v3(49.05,8.85)
O_10V: length 51.4
  TOP w0.35: 88.58,51.5 90.03,51.5 ; 90.03,51.5 90.03,51.38 ; 90.03,51.5 IC3.6 ; 90.03,51.38 90.03,51.08 ; 90.03,51.38 89.72,51.38 ; 90.03,51.08 90.25,50.85 91.1,50.85 ; 90.03,51.08 89.72,51.38 ; 89.72,51.38 88.58,51.38
  TOP w0.5: R93.2 v1(83.1,33.95) ; v1(87.5,42.2) R64.2
  TOP w0.6: C81.2 79.1,29.95 79.5,29.55 IC10.2
  TOP w0.7: R55.2 C41.2 82.95,51.55 TP25.1 ; v1(83.1,33.95) 84.1,34.95 v2(84.1,39.65) FB3.1 ; v1(75.7,29.95) C81.2
  CONDUCTIVE3 w0.5: v1(87.5,42.2) 84.95,39.65 v2(84.1,39.65)
  CONDUCTIVE3 w0.7: v1(75.7,29.95) 79.1,29.95 v1(83.1,33.95)
  CONDUCTIVE3 w1: v2(84.1,39.65) 82.85,40.9 82.85,51.4
OGND: length 140.1
  TOP w0.2: 75.72,41.3 75.67,41.3 75.67,40.85 75.62,40.85
  TOP w0.3: 78.55,31.35 79.2,31.35 ; 79.1,40.7 C53.2 79.1,38.62 ; TP24.1 86.05,21.3 ; TP24.1 84.85,20.1 ; TP24.1 83.65,21.3 ; TP24.1 84.85,22.5 ; IC4.2 72.7,38.82 ; IC4.2 73.81,39.92 ; IC4.2 73.81,37.7 ; IC4.2 74.92,38.82 ; IC9.2 73.81,32.37 ; IC9.2 74.96,31.22 ; IC9.2 72.66,31.22 ; IC9.2 73.81,30.07 ; C83.1 75.9,29.15 ; C83.1 v1(76.85,28.45) ; C83.1 75.15,28.45 ; TP27.1 86.83,46.48 ; TP27.1 88,45.3 ; TP27.1 85.65,45.3 ; 75.62,40.85 D5.1 73.8,40.85 ; 75.72,41.3 C52.2 77.72,41.3 ; 81.85,27.85 R92.1 v1(82.75,27.05) ; 81.4,24 C82.2 81.97,24.6 ; D12.1 81.33,28.98 ; 77.62,48.05 79.38,48.05 ; C81.1 76.25,31.35 ; D8.1 v1(78.5,48.9) ; 82.17,28.98 82.17,28.27
  TOP w0.5: D5.1 v1(74.88,39.9) ; T5.9 87.5,61.27 ; T5.9 88.88,62.7 ; T5.9 87.5,64.1 ; T5.9 86.12,62.7 ; C53.2 78.35,39.65 ; 78.55,31.35 v1(78.55,32.35) ; 78.55,31.35 C81.1 77.05,32.15 ; 78.55,31.35 IC10.5 ; 90.9,56.12 90.9,56.7 ; C49.1 106.9,79.42 ; C49.1 105.45,79.42 ; C49.1 106.9,77.97 ; C49.1 105.47,78 ; C52.2 76.67,40.55 ; v1(83.15,28.98) D12.1
  CONDUCTIVE2 w0.25: IC4.2 72.7,38.82 ; IC4.2 73.81,39.92 ; IC4.2 73.81,37.7 ; IC4.2 74.92,38.82
  CONDUCTIVE2 w0.3: IC9.2 72.66,31.22 ; IC9.2 74.96,31.22 ; IC9.2 73.81,32.37 ; IC9.2 73.81,30.07 ; TP27.1 86.83,46.48 ; TP27.1 88,45.3 ; TP27.1 85.65,45.3 ; TP24.1 84.85,20.1 ; TP24.1 86.05,21.3 ; TP24.1 83.65,21.3 ; TP24.1 84.85,22.5
  CONDUCTIVE2 w0.5: T5.9 86.12,62.7 ; T5.9 87.5,64.1 ; T5.9 87.5,61.27 ; T5.9 88.88,62.7 ; C49.1 105.45,79.42 ; C49.1 105.47,78 ; C49.1 106.9,77.97 ; C49.1 106.9,79.42
  CONDUCTIVE3 w0.25: IC4.2 73.81,39.92 ; IC4.2 73.81,37.7 ; IC4.2 72.72,38.82 ; IC4.2 74.92,38.82
  CONDUCTIVE3 w0.3: TP24.1 84.85,20.1 ; TP24.1 86.05,21.3 ; TP24.1 84.85,22.5 ; TP24.1 83.65,21.3 ; IC9.2 72.66,31.22 ; IC9.2 74.96,31.22 ; IC9.2 73.81,32.37 ; IC9.2 73.81,30.07 ; TP27.1 88,45.3 ; TP27.1 85.65,45.3 ; TP27.1 86.83,46.48
  CONDUCTIVE3 w0.5: T5.9 87.5,61.27 ; T5.9 86.12,62.7 ; T5.9 88.88,62.7 ; T5.9 87.5,64.1 ; C49.1 106.9,77.97 ; C49.1 105.45,79.42 ; C49.1 105.47,78 ; C49.1 106.9,79.42
  BOTTOM w0.25: IC4.2 72.75,38.82 ; IC4.2 73.81,37.7 ; IC4.2 74.95,38.82 ; IC4.2 73.81,39.95
  BOTTOM w0.3: IC9.2 72.66,31.22 ; IC9.2 73.81,32.37 ; IC9.2 74.96,31.22 ; IC9.2 73.81,30.07 ; TP24.1 83.65,21.3 ; TP24.1 86.05,21.3 ; TP24.1 84.85,20.1 ; TP24.1 84.85,22.5 ; TP27.1 88,45.3 ; TP27.1 86.83,46.48 ; TP27.1 85.65,45.3 ; R102.1 101.65,68.92 ; R101.1 104.35,78.7
  BOTTOM w0.5: 103.65,77.95 R101.1 103.65,79.45 ; T5.9 86.12,62.7 ; T5.9 87.5,61.27 ; T5.9 88.88,62.7 ; T5.9 87.5,64.1 ; 103.8,99.5 R104.1 104.53,98.75 ; C49.1 106.9,79.42 ; C49.1 106.9,77.97 ; C49.1 105.45,79.42 ; C49.1 105.47,78 ; 101.55,91.38 101.55,90.65 102.25,90.65 ; 100.95,69.67 R102.1 100.95,68.2
  vias: v1(72.9,108.05) v1(72.9,103.25) v1(72.9,98) v1(72.9,92.75) v1(72.9,87.5) v1(72.9,82.25) v1(72.9,77) v1(72.9,71.75) v1(72.9,66.5) v1(72.9,61.25) v1(72.9,51.5) v1(72.9,46.5) v1(72.9,41.25) v1(72.9,35.25) v1(72.9,32.7) v1(72.9,27.45) v1(72.9,22.4) v1(72.9,17.4) v1(72.9,12.1) v1(72.9,6.8) v1(73,112.9) v1(73,1.5) v1(73.45,56.6) v1(73.45,55.75) v1(73.45,54.9) v1(73.45,54.05) v1(73.45,53.2) v1(73.45,52.35) v1(74.3,56.6) v1(74.3,55.75) v1(74.3,54.9) v1(74.3,54.05) v1(74.3,53.2) v1(74.3,52.35) v1(74.7,37.55) v1(74.78,29.7) v1(75.58,57.58) v1(75.58,52.27) v1(75.6,47.8) v1(76.1,35.3) v1(76.55,26.1) v1(76.72,40.4) v1(77.05,32.25) v1(77.78,58.6) v1(77.78,53) v1(78,113) v1(78,1.4) v1(78.2,108.05) v1(78.2,103.25) v1(78.2,98) v1(78.2,92.75) v1(78.2,87.5) v1(78.2,82.25) v1(78.2,77) v1(78.2,71.75) v1(78.2,66.5) v1(78.2,39.65) v1(78.25,21.2) v1(78.25,15.9) v1(78.25,10.6) v1(78.25,5.3) v1(78.55,42.25) v1(78.6,62.55) v1(78.62,36.77) v1(79.47,27.48) v1(79.58,38.4) v1(79.7,50.35) v1(79.65,45.85) v1(80.67,32.85) v1(80.75,53.77) v1(80.9,50.3) v1(81.8,45.5) v1(81.8,40.7) v1(82.08,53.73) v1(82.2,63.02) v1(82.17,24.62) v1(82.72,34.9) v1(82.83,66.8) v1(83,113) v1(83.03,59.08) v1(83,1.4) v1(83.15,38.6) v1(83.15,36.9) v1(83.35,32.88) v1(83.5,108.05) v1(83.5,103.25) v1(83.5,98) v1(83.5,92.75) v1(83.5,87.5) v1(83.5,82.25) v1(83.5,77) v1(83.5,71.75) v1(83.95,47.25) v1(84,45.85) v1(84.05,15.9) v1(84.05,10.6) v1(84.05,5.3) v1(84.65,40.6) v1(85.05,36.9) v1(85.47,101.1) v1(85.47,96.33) v1(85.47,91.03) v1(85.47,85.72) v1(85.47,80.42) v1(85.88,75.12) v1(85.9,54.73) v1(86.08,66.6) v1(86.25,106.12) v1(86.35,47.1) v1(86.47,68.83) v1(86.5,38.45) v1(86.85,56.85) v1(87.33,55.55) v1(87.6,30.95) v1(87.7,26.65) v1(87.7,24.88) v1(88,113) v1(88.05,71.03) v1(88,1.4) v1(88.4,59.23) v1(88.55,53.02) v1(88.6,46.7) v1(88.8,60.62) v1(89.12,44.67) v1(89.17,43.42) v1(89.17,41.17) v1(89.5,39.25) v1(89.85,21.2) v1(89.85,15.9) v1(89.85,10.6) v1(89.85,5.3) v1(90.17,110.05) v1(90.22,59.5) v1(90.38,35.67) v1(90.7,66.95) v1(90.72,44.67) v1(90.67,43.42) v1(90.7,41.2) v1(90.88,57.4) v1(91.15,60.42) v1(92.3,30.7) v1(92.4,26.65) v1(92.42,24.88) v1(93,113) v1(93,1.4) v1(93.4,62.7) v1(93.42,47.58) v1(93.42,46.17) v1(93.67,43.7) v1(93.7,20.27) v1(93.7,19.43) v1(93.7,18.57) v1(94.55,20.27) v1(94.55,19.43) v1(94.55,18.57) v1(94.6,44.6) v1(94.58,35.05) v1(94.67,46.27) v1(94.78,60.12) v1(94.75,56.3) v1(95.03,38.98) v1(95.4,20.27) v1(95.4,19.43) v1(95.4,18.57) v1(95.5,65.05) v1(95.65,10.6) v1(95.65,5.3) v1(95.75,43.7) v1(96.17,44.6) v1(96.25,20.25) v1(96.25,19.4) v1(96.25,18.55) v1(96.8,58.35) v1(97.1,20.25) v1(97.1,19.4) v1(97.1,18.55) v1(97.1,17.7) v1(97.1,16.85) v1(97.1,16) v1(97.1,15.15) v1(98,113) v1(98.03,62.67) v1(97.95,20.25) v1(97.95,19.4) v1(97.95,18.55) v1(97.95,17.7) v1(97.95,16.85) v1(97.95,16) v1(97.95,15.15) v1(98,1.4) v1(98.25,44.6) v1(98.22,43.7) v1(98.28,111.47) v1(98.5,36.73) v1(98.8,20.25) v1(98.8,19.4) v1(98.8,18.55) v1(98.8,17.7) v1(98.8,16.85) v1(98.8,16) v1(98.8,15.15) v1(99,56.3) v1(99.65,20.25) v1(99.65,19.4) v1(99.65,18.55) v1(99.65,17.7) v1(99.65,16.85) v1(99.65,16) v1(99.65,15.15) v1(99.8,44.65) v1(99.8,43.7) v1(99.95,38.17) v1(100.5,19.4) v1(100.5,18.55) v1(100.5,17.7) v1(100.5,16.85) v1(100.5,16) v1(100.5,15.15) v1(100.6,88.4) v1(100.7,58.5) v1(100.83,62.33) v1(101.3,36.73) v1(101.35,18.55) v1(101.35,17.7) v1(101.35,16.85) v1(101.35,16) v1(101.35,15.15) v1(101.42,50.58) v1(101.42,49.27) v1(101.45,10.6) v1(101.45,5.3) v1(101.7,75.1) v1(101.67,74.35) v1(101.67,73.6) v1(101.67,72.85) v1(101.85,54.33) v1(101.92,44.65) v1(101.92,43.7) v1(101.92,40.58) v1(102.65,61.7) v1(102.7,52.23) v1(102.7,48.55) v1(102.75,88.83) v1(102.78,58.5) v1(103,113) v1(103,1.4) v1(103.2,55.75) v1(103.65,52.27) v1(103.65,47.98) v1(104.17,107.2) v1(104.95,61.5) v1(105.4,110.28) v1(106.4,20.25) v1(106.75,49.25) v1(106.75,41.6) v1(107.25,15.9) v1(107.25,10.6) v1(107.25,5.3) v1(107.85,72.08) v1(107.85,71.22) v1(107.85,70.38) v1(107.85,69.53) v1(107.85,68.67) v1(107.85,67.83) v1(107.85,66.97) v1(107.85,66.12) v1(107.85,65.28) v1(107.85,64.42) v1(107.85,63.58) v1(107.85,62.73) v1(107.85,61.88) v1(107.85,61.02) v1(107.85,60.17) v1(107.85,59.33) v1(107.85,58.48) v1(107.85,57.62) v1(107.85,56.77) v1(107.85,55.92) v1(108,113) v1(108,1.4) v1(108.25,36.75) v1(108.7,72.92) v1(108.7,72.08) v1(108.7,71.22) v1(108.7,70.38) v1(108.7,69.53) v1(108.7,68.67) v1(108.7,67.83) v1(108.7,66.97) v1(108.7,66.12) v1(108.7,65.28) v1(108.7,64.42) v1(108.7,63.58) v1(108.7,62.73) v1(108.7,61.88) v1(108.7,61.02) v1(108.7,60.17) v1(108.7,59.33) v1(108.7,58.48) v1(108.7,57.62) v1(108.7,56.77) v1(108.7,55.92) v1(109.55,88.83) v1(109.55,73.78) v1(109.55,72.92) v1(109.55,72.08) v1(109.55,71.22) v1(109.55,70.38) v1(109.55,69.53) v1(109.55,68.67) v1(109.5,63.02) v1(109.55,57.38) v1(109.55,56.52) v1(109.55,55.67) v1(109.55,54.83) v1(110.35,63.02) v1(110.4,71.08) v1(110.4,68.67) v1(110.4,57.38) v1(110.4,56.52) v1(110.4,55.67) v1(110.4,54.83) v1(110.8,49.9) v1(110.8,44.6) v1(110.8,39.3) v1(111,107.2) v1(111,20.25) v1(113,113) v1(113.05,15.9) v1(113.05,10.6) v1(113.05,5.3) v1(113,1.4) v1(115.35,20.5) v1(115.55,110.28) v1(116.95,106.92) v1(118,113) v1(118,1.4) v1(118.85,15.9) v1(118.85,10.6) v1(118.85,5.3) v1(119.1,24.25) v1(120.45,21.2) v1(121.4,113) v1(121.4,1.4) v1(121.8,108.2) v1(121.8,6.2) v1(122.42,101.45) v1(122.85,28) v1(124.65,15.9) v1(125.4,104.6) v1(125.4,9.8) v1(126.25,26.5) v1(126.25,21.2) v1(126.6,31.75) v1(127.3,70.8) v1(127.3,65.05) v1(127.3,59.45) v1(127.3,53.85) v1(127.3,48.25) v1(127.3,42.65) v1(127.3,37.05) v1(127.45,100.95) v1(127.5,95.9) v1(127.53,89.85) v1(128.7,85.55) v1(128.7,80.25) v1(128.7,74.95) v1(130.2,104.2) v1(130.2,94.7) v1(130.2,89.45) v1(130.2,84.2) v1(130.2,78.95) v1(130.2,73.7) v1(130.2,68.45) v1(130.2,63.2) v1(130.2,57.95) v1(130.2,52.7) v1(130.2,47.45) v1(130.2,42.2) v1(130.2,36.95) v1(130.2,31.7) v1(130.2,26.45) v1(130.2,21.2) v1(130.2,15.95) v1(130.2,10.2) v3(92.9,53.42) v3(92.9,52.62) v3(92.9,51.83) v3(92.9,51.02) v3(92.9,50.23) v3(93.65,53.42) v3(93.65,52.62) v3(93.65,51.83) v3(93.65,51.02) v3(93.65,50.23) v3(94.4,53.42) v3(94.4,52.62) v3(94.4,51.83) v3(94.4,51.02) v3(94.4,50.23) v3(95.15,53.42) v3(95.15,52.62) v3(95.15,51.83) v3(95.15,51.02) v3(95.15,50.23)
N551939: length 54.9
  TOP w0.3: v1(100.7,57.23) 100.7,55.33 100.9,55.12 ; v1(94.25,59.23) R53.2
  CONDUCTIVE2 w0.3: v1(94.25,59.23) 98.7,59.23 v1(100.7,57.23) 101.75,58.27 101.75,62.33 102.2,62.77 102.2,72.15 102.6,72.55 102.6,80.05 102.25,80.4 102.25,84.11 99.7,86.66 99.7,96.95 98,98.65 v3(97.88,98.65)
  vias: v1(87.25,96.05) v1(87.25,95.2) v1(87.25,94.35) v1(88.1,98.9) v1(88.1,96.05) v1(88.1,95.2) v1(88.1,94.35) v1(88.1,91.25) v1(88.95,99.75) v1(88.95,98.9) v1(88.95,98.05) v1(88.95,97.2) v1(88.95,96.35) v1(88.95,95.5) v1(88.95,94.65) v1(88.95,93.8) v1(88.95,92.95) v1(88.95,92.1) v1(88.95,91.25) v1(89.8,99.75) v1(89.8,98.9) v1(89.8,98.05) v1(89.8,97.2) v1(89.8,96.35) v1(89.8,95.5) v1(89.8,94.65) v1(89.8,93.8) v1(89.8,92.95) v1(89.8,92.1) v1(89.8,91.25) v1(90.65,99.75) v1(90.65,98.9) v1(90.65,98.05) v1(90.65,97.2) v1(90.65,96.35) v1(90.65,95.5) v1(90.65,94.65) v1(90.65,93.8) v1(90.65,92.95) v1(90.65,92.1) v1(90.65,91.25) v1(91.5,99.75) v1(91.5,98.9) v1(91.5,98.05) v1(91.5,97.2) v1(91.5,96.35) v1(91.5,95.5) v1(91.5,94.65) v1(91.5,93.8) v1(91.5,92.95) v1(91.5,92.1) v1(91.5,91.25) v3(93.78,109.97) v3(93.78,109.17) v3(93.78,108.38) v3(93.78,107.58) v3(93.78,106.78) v3(94.58,109.97) v3(94.58,109.17) v3(94.58,108.38) v3(94.58,107.58) v3(94.58,106.78) v3(94.67,102.65) v3(94.67,101.85) v3(94.67,101.05) v3(94.67,100.25) v3(94.67,99.45) v3(94.67,98.65) v3(94.67,96.15) v3(94.67,95.35) v3(94.67,94.55) v3(94.67,93.75) v3(94.67,92.95) v3(94.67,92.15) v3(95.38,109.97) v3(95.38,109.17) v3(95.38,108.38) v3(95.38,107.58) v3(95.38,106.78) v3(95.47,102.65) v3(95.47,101.85) v3(95.47,101.05) v3(95.47,100.25) v3(95.47,99.45) v3(95.47,98.65) v3(95.47,96.15) v3(95.47,95.35) v3(95.47,94.55) v3(95.47,93.75) v3(95.47,92.95) v3(95.47,92.15) v3(96.17,109.97) v3(96.17,109.17) v3(96.17,108.38) v3(96.17,107.58) v3(96.17,106.78) v3(96.28,102.65) v3(96.28,101.85) v3(96.28,101.05) v3(96.28,100.25) v3(96.28,99.45) v3(96.28,98.65) v3(96.28,96.15) v3(96.28,95.35) v3(96.28,94.55) v3(96.28,93.75) v3(96.28,92.95) v3(96.28,92.15) v3(96.97,109.97) v3(96.97,109.17) v3(96.97,108.38) v3(96.97,107.58) v3(96.97,106.78) v3(97.08,102.65) v3(97.08,101.85) v3(97.08,101.05) v3(97.08,100.25) v3(97.08,99.45) v3(97.08,98.65) v3(97.08,96.15) v3(97.08,95.35) v3(97.08,94.55) v3(97.08,93.75) v3(97.08,92.95) v3(97.08,92.15) v3(97.78,109.97) v3(97.78,109.17) v3(97.78,108.38) v3(97.78,107.58) v3(97.78,106.78) v3(97.88,102.65) v3(97.88,101.85) v3(97.88,101.05) v3(97.88,100.25) v3(97.88,99.45) v3(97.88,96.15) v3(97.88,95.35) v3(97.88,94.55) v3(97.88,93.75) v3(97.88,92.95) v3(97.88,92.15)
N551985:
  vias: v1(47.62,82.17) v1(47.62,81.33) v1(47.62,80.47) v1(47.62,79.62) v1(47.62,78.78) v1(47.62,77.92) v1(47.62,77.08) v1(47.62,76.22) v1(48.48,82.17) v1(48.48,81.33) v1(48.48,80.47) v1(48.48,79.62) v1(48.48,78.78) v1(48.48,77.92) v1(48.48,77.08) v1(48.48,76.22) v1(49.33,82.17) v1(49.33,81.33) v1(49.33,80.47) v1(49.33,79.62) v1(49.33,78.78) v1(49.33,77.92) v1(49.33,77.08) v1(49.33,76.22) v1(50.17,82.17) v1(50.17,81.33) v1(50.17,80.47) v1(50.17,79.62) v1(50.17,78.78) v1(50.17,77.92) v1(50.17,77.08) v1(50.17,76.22) v1(51.02,82.17) v1(51.02,81.33) v1(51.02,80.47) v1(51.02,79.62) v1(51.02,78.78) v1(51.02,77.92) v1(51.02,77.08) v1(51.02,76.22)
N552199: length 30.1
  TOP w0.3: R65.2 C46.1 v1(100.92,45.33)
  TOP w0.6: v1(82.75,25.75) R91.1
  CONDUCTIVE3 w0.5: v1(100.92,45.33) 100.92,37.74 CN4.1
  CONDUCTIVE3 w0.6: v1(82.75,25.75) 93.45,25.75
  vias: v1(93.45,29.4) v1(93.45,28.55) v1(93.45,27.7) v1(93.45,26.85) v1(93.45,26) v1(93.45,25.15) v1(94.3,29.4) v1(94.3,28.55) v1(94.3,27.7) v1(94.3,26.85) v1(94.3,26) v1(94.3,25.15) v1(95.15,29.4) v1(95.15,28.55) v1(95.15,27.7) v1(95.15,26.85) v1(95.15,26) v1(95.15,25.15) v1(96,29.4) v1(96,28.55) v1(96,27.7) v1(96,26.85) v1(96,26) v1(96,25.15) v1(96.85,29.4) v1(96.85,28.55) v1(96.85,27.7) v1(96.85,26.85) v1(96.85,26) v1(96.85,25.15) v1(97,31.1) v1(97,30.25) v1(97.7,29.4) v1(97.7,28.55) v1(97.7,27.7) v1(97.7,26.85) v1(97.7,26) v1(97.7,25.15) v1(97.85,30.25) v1(98.55,29.4) v1(98.55,28.55) v1(98.55,27.7) v1(98.55,26.85) v1(98.55,26) v1(98.55,25.15) v1(99.4,28.55) v1(99.4,27.7) v1(99.4,26.85) v1(99.4,26) v1(99.4,25.15) v1(114.35,70.53) v1(114.35,69.67) v1(114.35,68.83) v1(115.2,70.53) v1(115.2,69.67) v1(115.2,68.83) v1(116.05,70.53) v1(116.05,69.67) v1(116.05,68.83) v1(116.9,70.53) v1(116.9,69.67) v1(116.9,68.83) v1(116.9,67.97) v1(116.9,67.12) v1(116.9,66.28) v1(117.75,70.53) v1(117.75,69.67) v1(117.75,68.83) v1(117.75,67.97) v1(117.75,67.12) v1(117.75,66.28) v1(118.6,70.53) v1(118.6,69.67) v1(118.6,68.83) v1(118.6,67.97) v1(118.6,67.12) v1(118.6,66.28) v1(119.45,70.53) v1(119.45,69.67) v1(119.45,68.83) v1(119.45,67.97) v1(119.45,67.12) v1(119.45,66.28) v1(120.3,70.53) v1(120.3,69.67) v1(120.3,68.83) v1(120.3,67.97) v1(120.3,67.12) v1(120.3,66.28) v1(121.15,70.53) v1(121.15,69.67) v1(121.15,68.83) v1(121.15,67.97) v1(121.15,67.12) v1(121.15,66.28) v1(122,70.53) v1(122,69.67) v1(122,68.83) v1(122,67.97) v1(122,67.12) v1(122,66.28) v1(122.85,70.53) v1(122.85,69.67) v1(122.85,68.83) v1(122.85,67.97) v1(122.85,67.12) v1(122.85,66.28) v1(123.7,70.53) v1(123.7,69.67) v1(123.7,68.83) v1(123.7,67.97) v1(123.7,67.12) v1(123.7,66.28) v1(124.55,70.53) v1(124.55,69.67) v1(124.55,68.83) v1(124.55,67.97) v1(124.55,67.12) v1(124.55,66.28) v1(125.4,70.53) v1(125.4,69.67) v1(125.4,68.83) v1(125.4,67.97) v1(125.4,67.12) v1(125.4,66.28)
N552352:
  vias: v1(47.62,97.97) v1(47.62,97.12) v1(47.62,96.28) v1(47.62,95.42) v1(47.62,94.58) v1(47.62,93.72) v1(47.62,92.88) v1(47.62,92.03) v1(48.48,97.97) v1(48.48,97.12) v1(48.48,96.28) v1(48.48,95.42) v1(48.48,94.58) v1(48.48,93.72) v1(48.48,92.88) v1(48.48,92.03) v1(49.33,97.97) v1(49.33,97.12) v1(49.33,96.28) v1(49.33,95.42) v1(49.33,94.58) v1(49.33,93.72) v1(49.33,92.88) v1(49.33,92.03) v1(50.17,97.97) v1(50.17,97.12) v1(50.17,96.28) v1(50.17,95.42) v1(50.17,94.58) v1(50.17,93.72) v1(50.17,92.88) v1(50.17,92.03) v1(51.02,97.97) v1(51.02,97.12) v1(51.02,96.28) v1(51.02,95.42) v1(51.02,94.58) v1(51.02,93.72) v1(51.02,92.88) v1(51.02,92.03)
N552464: length 27.3
  TOP w0.3: v1(89.33,58.8) R51.2 89.33,57.88
  CONDUCTIVE2 w0.3: v3(97.72,78.45) 98.9,77.28 98.9,65.57 96.93,63.6 93.05,63.6 89.33,59.88 v1(89.33,58.8)
  vias: v1(87.25,81.05) v1(87.25,80.2) v1(87.25,79.35) v1(88.1,84.33) v1(88.1,81.05) v1(88.1,80.2) v1(88.1,79.35) v1(88.1,76.25) v1(88.95,84.75) v1(88.95,83.9) v1(88.95,83.05) v1(88.95,82.2) v1(88.95,81.35) v1(88.95,80.5) v1(88.95,79.65) v1(88.95,78.8) v1(88.95,77.95) v1(88.95,77.1) v1(88.95,76.25) v1(89.8,84.75) v1(89.8,83.9) v1(89.8,83.05) v1(89.8,82.2) v1(89.8,81.35) v1(89.8,80.5) v1(89.8,79.65) v1(89.8,78.8) v1(89.8,77.95) v1(89.8,77.1) v1(89.8,76.25) v1(90.65,84.75) v1(90.65,83.9) v1(90.65,83.05) v1(90.65,82.2) v1(90.65,81.35) v1(90.65,80.5) v1(90.65,79.65) v1(90.65,78.8) v1(90.65,77.95) v1(90.65,77.1) v1(90.65,76.25) v1(91.5,84.75) v1(91.5,83.9) v1(91.5,83.05) v1(91.5,82.2) v1(91.5,81.35) v1(91.5,80.5) v1(91.5,79.65) v1(91.5,78.8) v1(91.5,77.95) v1(91.5,77.1) v1(91.5,76.25) v3(94.53,82.45) v3(94.53,81.65) v3(94.53,80.85) v3(94.53,80.05) v3(94.53,79.25) v3(94.53,78.45) v3(94.53,74.33) v3(94.53,73.53) v3(94.53,72.72) v3(94.53,71.92) v3(94.53,71.12) v3(94.53,70.33) v3(95.33,82.45) v3(95.33,81.65) v3(95.33,80.85) v3(95.33,80.05) v3(95.33,79.25) v3(95.33,78.45) v3(95.33,74.33) v3(95.33,73.53) v3(95.33,72.72) v3(95.33,71.92) v3(95.33,71.12) v3(95.33,70.33) v3(96.12,82.45) v3(96.12,81.65) v3(96.12,80.85) v3(96.12,80.05) v3(96.12,79.25) v3(96.12,78.45) v3(96.12,74.33) v3(96.12,73.53) v3(96.12,72.72) v3(96.12,71.92) v3(96.12,71.12) v3(96.12,70.33) v3(96.92,82.45) v3(96.92,81.65) v3(96.92,80.85) v3(96.92,80.05) v3(96.92,79.25) v3(96.92,78.45) v3(96.92,74.33) v3(96.92,73.53) v3(96.92,72.72) v3(96.92,71.92) v3(96.92,71.12) v3(96.92,70.33) v3(97.72,82.45) v3(97.72,81.65) v3(97.72,80.85) v3(97.72,80.05) v3(97.72,79.25) v3(97.72,74.33) v3(97.72,73.53) v3(97.72,72.72) v3(97.72,71.92) v3(97.72,71.12) v3(97.72,70.33)
